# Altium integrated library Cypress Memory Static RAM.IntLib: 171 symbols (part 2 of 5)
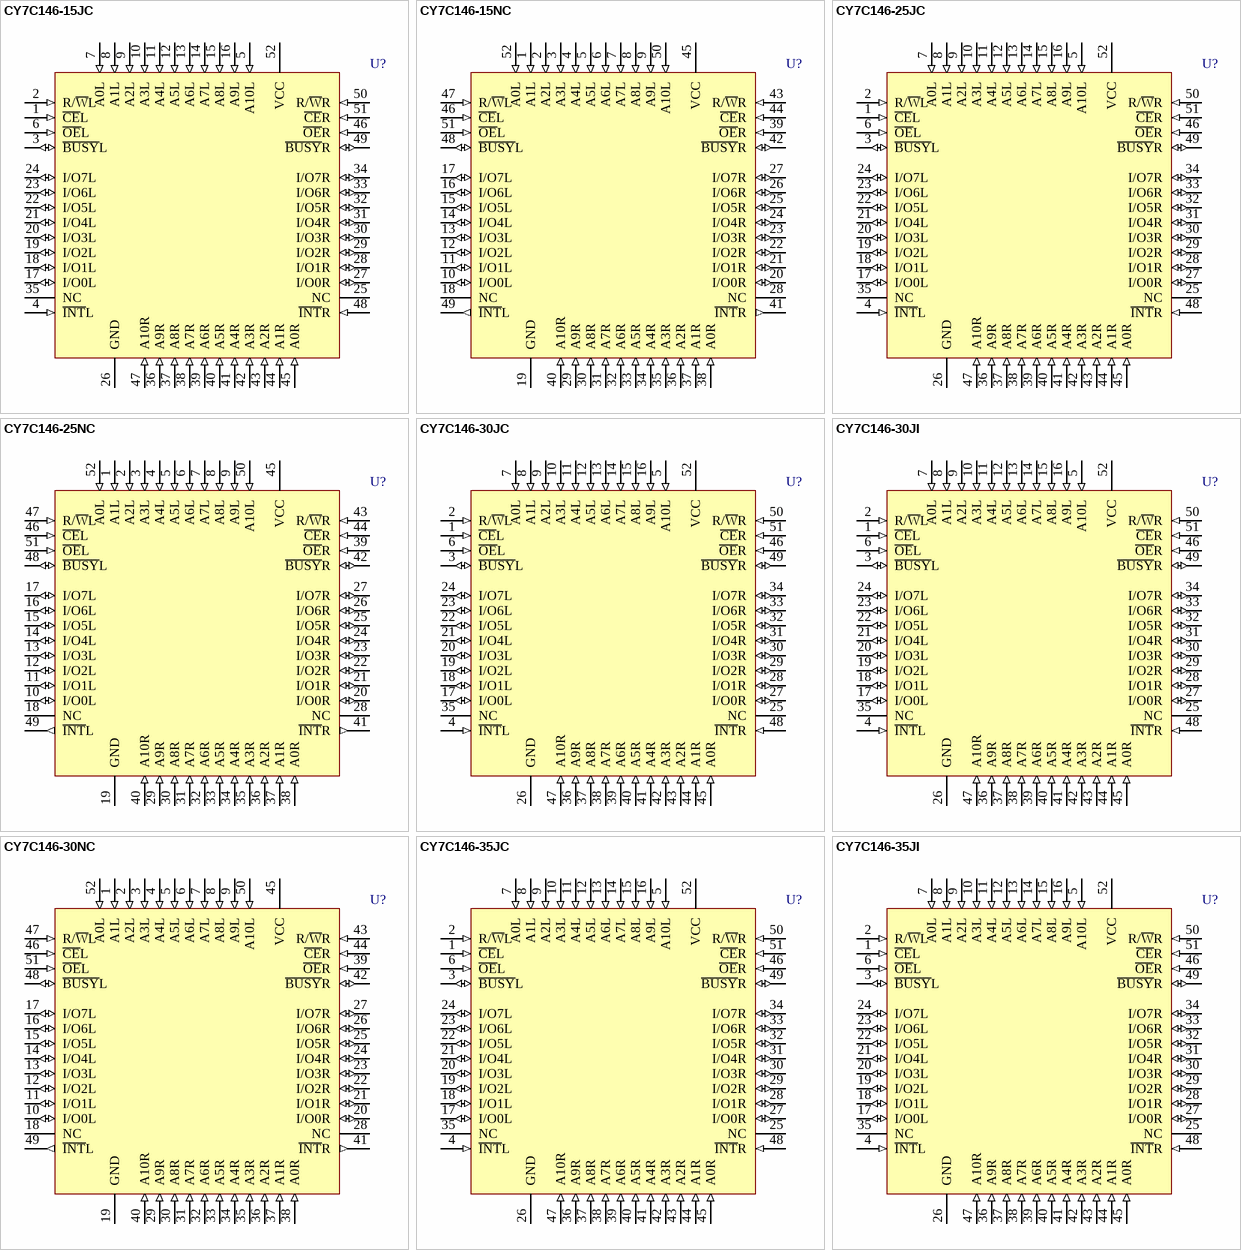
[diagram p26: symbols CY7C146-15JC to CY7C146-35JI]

## CY7C146-35JC
designator U?
2K x 8 Dual-Port Static RAM
footprint J69_N (Leaded Chip Carrier, 52-Leads, Body 19x19mm, Pitch 1.27mm, IPC Medium Density)
footprint J69_L (Leaded Chip Carrier, 52-Leads, Body 19x19mm, Pitch 1.27mm, IPC High Density)
footprint J69_M (Leaded Chip Carrier, 52-Leads, Body 19x19mm, Pitch 1.27mm, IPC Low Density)
3D model CY7C146-J69 (52-Pin Plastic Leaded Chip Carrier 1.27 mm Pitch)
pins: 1 ~{CE}L (in), 2 R/~{W}L (in), 3 ~{BUSY}L (io), 4 ~{INT}L (in), 5 A10L (in), 6 ~{OE}L (in), 7 A0L (in), 8 A1L (in), 9 A2L (in), 10 A3L (in), 11 A4L (in), 12 A5L (in), 13 A6L (in), 14 A7L (in), 15 A8L (in), 16 A9L (in), 17 I/O0L (io), 18 I/O1L (io), 19 I/O2L (io), 20 I/O3L (io), 21 I/O4L (io), 22 I/O5L (io), 23 I/O6L (io), 24 I/O7L (io), 25 NC, 26 GND (power), 27 I/O0R (io), 28 I/O1R (io), 29 I/O2R (io), 30 I/O3R (io), 31 I/O4R (io), 32 I/O5R (io), 33 I/O6R (io), 34 I/O7R (io), 35 NC, 36 A9R (in), 37 A8R (in), 38 A7R (in), 39 A6R (in), 40 A5R (in), 41 A4R (in), 42 A3R (in), 43 A2R (in), 44 A1R (in), 45 A0R (in), 46 ~{OE}R (in), 47 A10R (in), 48 ~{INT}R (in), 49 ~{BUSY}R (io), 50 R/~{W}R (in), 51 ~{CE}R (in), 52 VCC (power)

## CY7C146-35JI
designator U?
2K x 8 Dual-Port Static RAM
footprint J69_N (Leaded Chip Carrier, 52-Leads, Body 19x19mm, Pitch 1.27mm, IPC Medium Density)
footprint J69_L (Leaded Chip Carrier, 52-Leads, Body 19x19mm, Pitch 1.27mm, IPC High Density)
footprint J69_M (Leaded Chip Carrier, 52-Leads, Body 19x19mm, Pitch 1.27mm, IPC Low Density)
3D model CY7C146-J69 (52-Pin Plastic Leaded Chip Carrier 1.27 mm Pitch)
pins: 1 ~{CE}L (in), 2 R/~{W}L (in), 3 ~{BUSY}L (io), 4 ~{INT}L (in), 5 A10L (in), 6 ~{OE}L (in), 7 A0L (in), 8 A1L (in), 9 A2L (in), 10 A3L (in), 11 A4L (in), 12 A5L (in), 13 A6L (in), 14 A7L (in), 15 A8L (in), 16 A9L (in), 17 I/O0L (io), 18 I/O1L (io), 19 I/O2L (io), 20 I/O3L (io), 21 I/O4L (io), 22 I/O5L (io), 23 I/O6L (io), 24 I/O7L (io), 25 NC, 26 GND (power), 27 I/O0R (io), 28 I/O1R (io), 29 I/O2R (io), 30 I/O3R (io), 31 I/O4R (io), 32 I/O5R (io), 33 I/O6R (io), 34 I/O7R (io), 35 NC, 36 A9R (in), 37 A8R (in), 38 A7R (in), 39 A6R (in), 40 A5R (in), 41 A4R (in), 42 A3R (in), 43 A2R (in), 44 A1R (in), 45 A0R (in), 46 ~{OE}R (in), 47 A10R (in), 48 ~{INT}R (in), 49 ~{BUSY}R (io), 50 R/~{W}R (in), 51 ~{CE}R (in), 52 VCC (power)

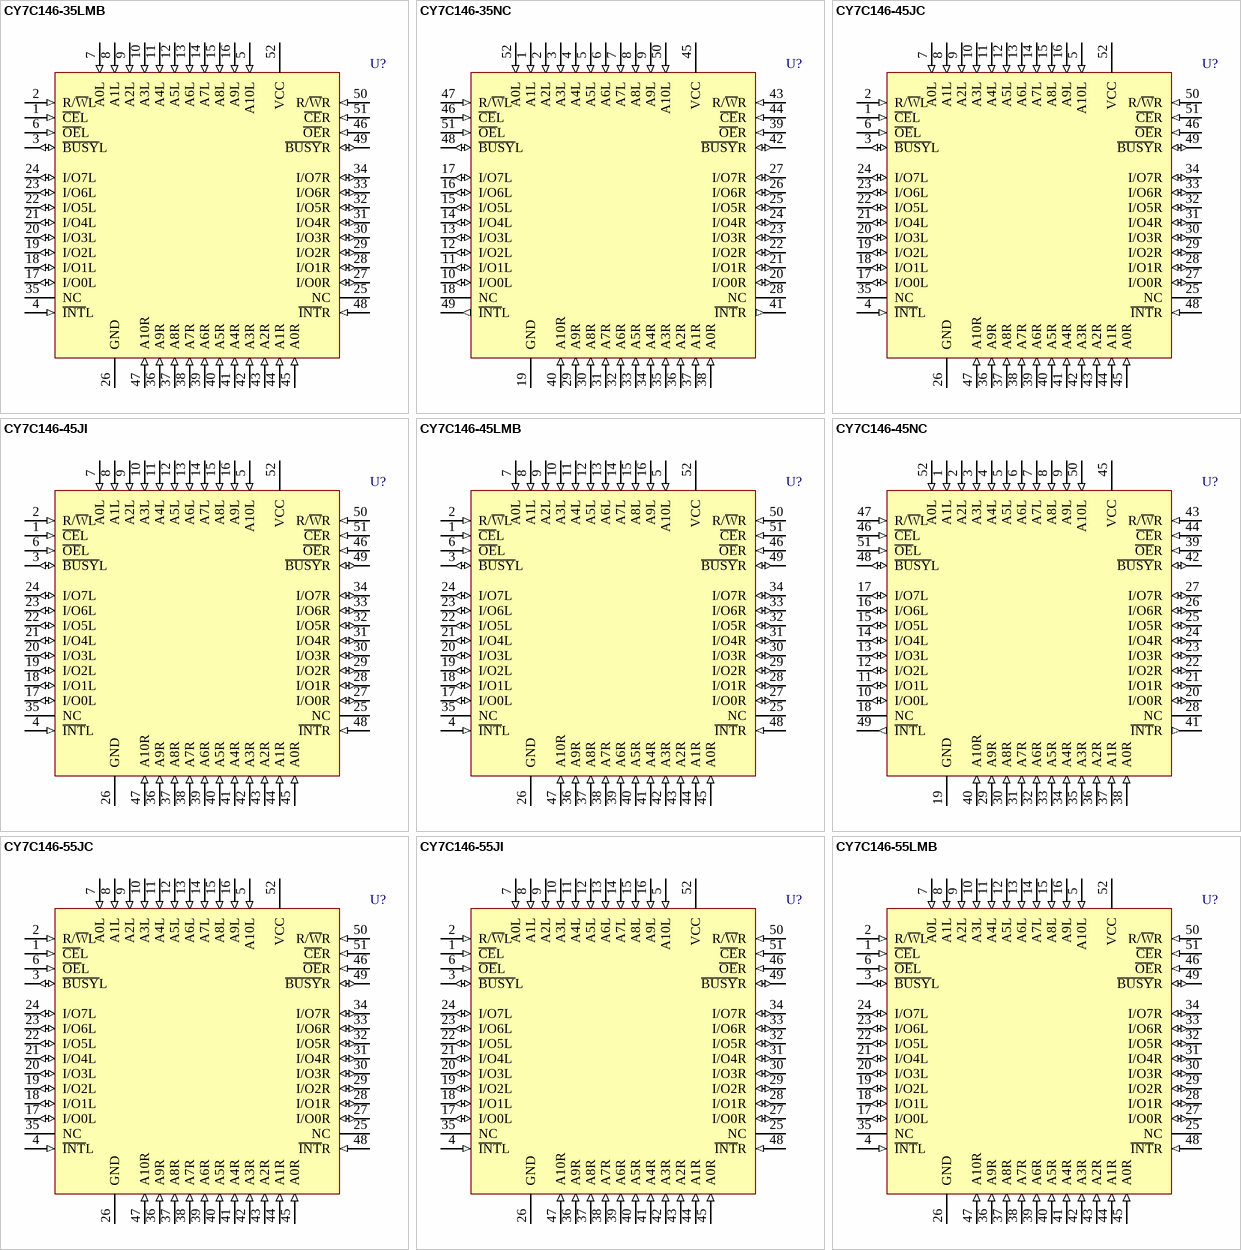
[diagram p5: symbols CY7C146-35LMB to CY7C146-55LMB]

## CY7C146-35LMB
designator U?
2K x 8 Dual-Port Static RAM
footprint L69 (Leadless Chip Carrier; 52 Terminals; Body 19.1 x 19.1 mm)
pins: 1 ~{CE}L (in), 2 R/~{W}L (in), 3 ~{BUSY}L (io), 4 ~{INT}L (in), 5 A10L (in), 6 ~{OE}L (in), 7 A0L (in), 8 A1L (in), 9 A2L (in), 10 A3L (in), 11 A4L (in), 12 A5L (in), 13 A6L (in), 14 A7L (in), 15 A8L (in), 16 A9L (in), 17 I/O0L (io), 18 I/O1L (io), 19 I/O2L (io), 20 I/O3L (io), 21 I/O4L (io), 22 I/O5L (io), 23 I/O6L (io), 24 I/O7L (io), 25 NC, 26 GND (power), 27 I/O0R (io), 28 I/O1R (io), 29 I/O2R (io), 30 I/O3R (io), 31 I/O4R (io), 32 I/O5R (io), 33 I/O6R (io), 34 I/O7R (io), 35 NC, 36 A9R (in), 37 A8R (in), 38 A7R (in), 39 A6R (in), 40 A5R (in), 41 A4R (in), 42 A3R (in), 43 A2R (in), 44 A1R (in), 45 A0R (in), 46 ~{OE}R (in), 47 A10R (in), 48 ~{INT}R (in), 49 ~{BUSY}R (io), 50 R/~{W}R (in), 51 ~{CE}R (in), 52 VCC (power)

## CY7C146-35NC
designator U?
2K x 8 Dual-Port Static RAM
footprint N52_N (QFP, 52-Leads, Body 10 x 10mm, Pitch 0.65mm, IPC Medium Density)
footprint N52_L (QFP, 52-Leads, Body 10 x 10mm, Pitch 0.65mm, IPC High Density)
footprint N52_M (QFP, 52-Leads, Body 10 x 10mm, Pitch 0.65mm, IPC Low Density)
3D model CY7C146-N52 (52-Pin Plastic Quad Flat Pack 0.65 mm Pitch)
pins: 1 A1L (in), 2 A2L (in), 3 A3L (in), 4 A4L (in), 5 A5L (in), 6 A6L (in), 7 A7L (in), 8 A8L (in), 9 A9L (in), 10 I/O0L (io), 11 I/O1L (io), 12 I/O2L (io), 13 I/O3L (io), 14 I/O4L (io), 15 I/O5L (io), 16 I/O6L (io), 17 I/O7L (io), 18 NC, 19 GND (power), 20 I/O0R (io), 21 I/O1R (io), 22 I/O2R (io), 23 I/O3R (io), 24 I/O4R (io), 25 I/O5R (io), 26 I/O6R (io), 27 I/O7R (io), 28 NC, 29 A9R (in), 30 A8R (in), 31 A7R (in), 32 A6R (in), 33 A5R (in), 34 A4R (in), 35 A3R (in), 36 A2R (in), 37 A1R (in), 38 A0R (in), 39 ~{OE}R (in), 40 A10R (in), 41 ~{INT}R (out), 42 ~{BUSY}R (io), 43 R/~{W}R (in), 44 ~{CE}R (in), 45 VCC (power), 46 ~{CE}L (in), 47 R/~{W}L (in), 48 ~{BUSY}L (io), 49 ~{INT}L (out), 50 A10L (in), 51 ~{OE}L (in), 52 A0L (in)

## CY7C146-45JC
designator U?
2K x 8 Dual-Port Static RAM
footprint J69_N (Leaded Chip Carrier, 52-Leads, Body 19x19mm, Pitch 1.27mm, IPC Medium Density)
footprint J69_L (Leaded Chip Carrier, 52-Leads, Body 19x19mm, Pitch 1.27mm, IPC High Density)
footprint J69_M (Leaded Chip Carrier, 52-Leads, Body 19x19mm, Pitch 1.27mm, IPC Low Density)
3D model CY7C146-J69 (52-Pin Plastic Leaded Chip Carrier 1.27 mm Pitch)
pins: 1 ~{CE}L (in), 2 R/~{W}L (in), 3 ~{BUSY}L (io), 4 ~{INT}L (in), 5 A10L (in), 6 ~{OE}L (in), 7 A0L (in), 8 A1L (in), 9 A2L (in), 10 A3L (in), 11 A4L (in), 12 A5L (in), 13 A6L (in), 14 A7L (in), 15 A8L (in), 16 A9L (in), 17 I/O0L (io), 18 I/O1L (io), 19 I/O2L (io), 20 I/O3L (io), 21 I/O4L (io), 22 I/O5L (io), 23 I/O6L (io), 24 I/O7L (io), 25 NC, 26 GND (power), 27 I/O0R (io), 28 I/O1R (io), 29 I/O2R (io), 30 I/O3R (io), 31 I/O4R (io), 32 I/O5R (io), 33 I/O6R (io), 34 I/O7R (io), 35 NC, 36 A9R (in), 37 A8R (in), 38 A7R (in), 39 A6R (in), 40 A5R (in), 41 A4R (in), 42 A3R (in), 43 A2R (in), 44 A1R (in), 45 A0R (in), 46 ~{OE}R (in), 47 A10R (in), 48 ~{INT}R (in), 49 ~{BUSY}R (io), 50 R/~{W}R (in), 51 ~{CE}R (in), 52 VCC (power)

## CY7C146-45JI
designator U?
2K x 8 Dual-Port Static RAM
footprint J69_N (Leaded Chip Carrier, 52-Leads, Body 19x19mm, Pitch 1.27mm, IPC Medium Density)
footprint J69_L (Leaded Chip Carrier, 52-Leads, Body 19x19mm, Pitch 1.27mm, IPC High Density)
footprint J69_M (Leaded Chip Carrier, 52-Leads, Body 19x19mm, Pitch 1.27mm, IPC Low Density)
3D model CY7C146-J69 (52-Pin Plastic Leaded Chip Carrier 1.27 mm Pitch)
pins: 1 ~{CE}L (in), 2 R/~{W}L (in), 3 ~{BUSY}L (io), 4 ~{INT}L (in), 5 A10L (in), 6 ~{OE}L (in), 7 A0L (in), 8 A1L (in), 9 A2L (in), 10 A3L (in), 11 A4L (in), 12 A5L (in), 13 A6L (in), 14 A7L (in), 15 A8L (in), 16 A9L (in), 17 I/O0L (io), 18 I/O1L (io), 19 I/O2L (io), 20 I/O3L (io), 21 I/O4L (io), 22 I/O5L (io), 23 I/O6L (io), 24 I/O7L (io), 25 NC, 26 GND (power), 27 I/O0R (io), 28 I/O1R (io), 29 I/O2R (io), 30 I/O3R (io), 31 I/O4R (io), 32 I/O5R (io), 33 I/O6R (io), 34 I/O7R (io), 35 NC, 36 A9R (in), 37 A8R (in), 38 A7R (in), 39 A6R (in), 40 A5R (in), 41 A4R (in), 42 A3R (in), 43 A2R (in), 44 A1R (in), 45 A0R (in), 46 ~{OE}R (in), 47 A10R (in), 48 ~{INT}R (in), 49 ~{BUSY}R (io), 50 R/~{W}R (in), 51 ~{CE}R (in), 52 VCC (power)

## CY7C146-45LMB
designator U?
2K x 8 Dual-Port Static RAM
footprint L69 (Leadless Chip Carrier; 52 Terminals; Body 19.1 x 19.1 mm)
pins: 1 ~{CE}L (in), 2 R/~{W}L (in), 3 ~{BUSY}L (io), 4 ~{INT}L (in), 5 A10L (in), 6 ~{OE}L (in), 7 A0L (in), 8 A1L (in), 9 A2L (in), 10 A3L (in), 11 A4L (in), 12 A5L (in), 13 A6L (in), 14 A7L (in), 15 A8L (in), 16 A9L (in), 17 I/O0L (io), 18 I/O1L (io), 19 I/O2L (io), 20 I/O3L (io), 21 I/O4L (io), 22 I/O5L (io), 23 I/O6L (io), 24 I/O7L (io), 25 NC, 26 GND (power), 27 I/O0R (io), 28 I/O1R (io), 29 I/O2R (io), 30 I/O3R (io), 31 I/O4R (io), 32 I/O5R (io), 33 I/O6R (io), 34 I/O7R (io), 35 NC, 36 A9R (in), 37 A8R (in), 38 A7R (in), 39 A6R (in), 40 A5R (in), 41 A4R (in), 42 A3R (in), 43 A2R (in), 44 A1R (in), 45 A0R (in), 46 ~{OE}R (in), 47 A10R (in), 48 ~{INT}R (in), 49 ~{BUSY}R (io), 50 R/~{W}R (in), 51 ~{CE}R (in), 52 VCC (power)

## CY7C146-45NC
designator U?
2K x 8 Dual-Port Static RAM
footprint N52_N (QFP, 52-Leads, Body 10 x 10mm, Pitch 0.65mm, IPC Medium Density)
footprint N52_L (QFP, 52-Leads, Body 10 x 10mm, Pitch 0.65mm, IPC High Density)
footprint N52_M (QFP, 52-Leads, Body 10 x 10mm, Pitch 0.65mm, IPC Low Density)
3D model CY7C146-N52 (52-Pin Plastic Quad Flat Pack 0.65 mm Pitch)
pins: 1 A1L (in), 2 A2L (in), 3 A3L (in), 4 A4L (in), 5 A5L (in), 6 A6L (in), 7 A7L (in), 8 A8L (in), 9 A9L (in), 10 I/O0L (io), 11 I/O1L (io), 12 I/O2L (io), 13 I/O3L (io), 14 I/O4L (io), 15 I/O5L (io), 16 I/O6L (io), 17 I/O7L (io), 18 NC, 19 GND (power), 20 I/O0R (io), 21 I/O1R (io), 22 I/O2R (io), 23 I/O3R (io), 24 I/O4R (io), 25 I/O5R (io), 26 I/O6R (io), 27 I/O7R (io), 28 NC, 29 A9R (in), 30 A8R (in), 31 A7R (in), 32 A6R (in), 33 A5R (in), 34 A4R (in), 35 A3R (in), 36 A2R (in), 37 A1R (in), 38 A0R (in), 39 ~{OE}R (in), 40 A10R (in), 41 ~{INT}R (out), 42 ~{BUSY}R (io), 43 R/~{W}R (in), 44 ~{CE}R (in), 45 VCC (power), 46 ~{CE}L (in), 47 R/~{W}L (in), 48 ~{BUSY}L (io), 49 ~{INT}L (out), 50 A10L (in), 51 ~{OE}L (in), 52 A0L (in)

## CY7C146-55JC
designator U?
2K x 8 Dual-Port Static RAM
footprint J69_N (Leaded Chip Carrier, 52-Leads, Body 19x19mm, Pitch 1.27mm, IPC Medium Density)
footprint J69_L (Leaded Chip Carrier, 52-Leads, Body 19x19mm, Pitch 1.27mm, IPC High Density)
footprint J69_M (Leaded Chip Carrier, 52-Leads, Body 19x19mm, Pitch 1.27mm, IPC Low Density)
3D model CY7C146-J69 (52-Pin Plastic Leaded Chip Carrier 1.27 mm Pitch)
pins: 1 ~{CE}L (in), 2 R/~{W}L (in), 3 ~{BUSY}L (io), 4 ~{INT}L (in), 5 A10L (in), 6 ~{OE}L (in), 7 A0L (in), 8 A1L (in), 9 A2L (in), 10 A3L (in), 11 A4L (in), 12 A5L (in), 13 A6L (in), 14 A7L (in), 15 A8L (in), 16 A9L (in), 17 I/O0L (io), 18 I/O1L (io), 19 I/O2L (io), 20 I/O3L (io), 21 I/O4L (io), 22 I/O5L (io), 23 I/O6L (io), 24 I/O7L (io), 25 NC, 26 GND (power), 27 I/O0R (io), 28 I/O1R (io), 29 I/O2R (io), 30 I/O3R (io), 31 I/O4R (io), 32 I/O5R (io), 33 I/O6R (io), 34 I/O7R (io), 35 NC, 36 A9R (in), 37 A8R (in), 38 A7R (in), 39 A6R (in), 40 A5R (in), 41 A4R (in), 42 A3R (in), 43 A2R (in), 44 A1R (in), 45 A0R (in), 46 ~{OE}R (in), 47 A10R (in), 48 ~{INT}R (in), 49 ~{BUSY}R (io), 50 R/~{W}R (in), 51 ~{CE}R (in), 52 VCC (power)

## CY7C146-55JI
designator U?
2K x 8 Dual-Port Static RAM
footprint J69_N (Leaded Chip Carrier, 52-Leads, Body 19x19mm, Pitch 1.27mm, IPC Medium Density)
footprint J69_L (Leaded Chip Carrier, 52-Leads, Body 19x19mm, Pitch 1.27mm, IPC High Density)
footprint J69_M (Leaded Chip Carrier, 52-Leads, Body 19x19mm, Pitch 1.27mm, IPC Low Density)
3D model CY7C146-J69 (52-Pin Plastic Leaded Chip Carrier 1.27 mm Pitch)
pins: 1 ~{CE}L (in), 2 R/~{W}L (in), 3 ~{BUSY}L (io), 4 ~{INT}L (in), 5 A10L (in), 6 ~{OE}L (in), 7 A0L (in), 8 A1L (in), 9 A2L (in), 10 A3L (in), 11 A4L (in), 12 A5L (in), 13 A6L (in), 14 A7L (in), 15 A8L (in), 16 A9L (in), 17 I/O0L (io), 18 I/O1L (io), 19 I/O2L (io), 20 I/O3L (io), 21 I/O4L (io), 22 I/O5L (io), 23 I/O6L (io), 24 I/O7L (io), 25 NC, 26 GND (power), 27 I/O0R (io), 28 I/O1R (io), 29 I/O2R (io), 30 I/O3R (io), 31 I/O4R (io), 32 I/O5R (io), 33 I/O6R (io), 34 I/O7R (io), 35 NC, 36 A9R (in), 37 A8R (in), 38 A7R (in), 39 A6R (in), 40 A5R (in), 41 A4R (in), 42 A3R (in), 43 A2R (in), 44 A1R (in), 45 A0R (in), 46 ~{OE}R (in), 47 A10R (in), 48 ~{INT}R (in), 49 ~{BUSY}R (io), 50 R/~{W}R (in), 51 ~{CE}R (in), 52 VCC (power)

## CY7C146-55LMB
designator U?
2K x 8 Dual-Port Static RAM
footprint L69 (Leadless Chip Carrier; 52 Terminals; Body 19.1 x 19.1 mm)
pins: 1 ~{CE}L (in), 2 R/~{W}L (in), 3 ~{BUSY}L (io), 4 ~{INT}L (in), 5 A10L (in), 6 ~{OE}L (in), 7 A0L (in), 8 A1L (in), 9 A2L (in), 10 A3L (in), 11 A4L (in), 12 A5L (in), 13 A6L (in), 14 A7L (in), 15 A8L (in), 16 A9L (in), 17 I/O0L (io), 18 I/O1L (io), 19 I/O2L (io), 20 I/O3L (io), 21 I/O4L (io), 22 I/O5L (io), 23 I/O6L (io), 24 I/O7L (io), 25 NC, 26 GND (power), 27 I/O0R (io), 28 I/O1R (io), 29 I/O2R (io), 30 I/O3R (io), 31 I/O4R (io), 32 I/O5R (io), 33 I/O6R (io), 34 I/O7R (io), 35 NC, 36 A9R (in), 37 A8R (in), 38 A7R (in), 39 A6R (in), 40 A5R (in), 41 A4R (in), 42 A3R (in), 43 A2R (in), 44 A1R (in), 45 A0R (in), 46 ~{OE}R (in), 47 A10R (in), 48 ~{INT}R (in), 49 ~{BUSY}R (io), 50 R/~{W}R (in), 51 ~{CE}R (in), 52 VCC (power)

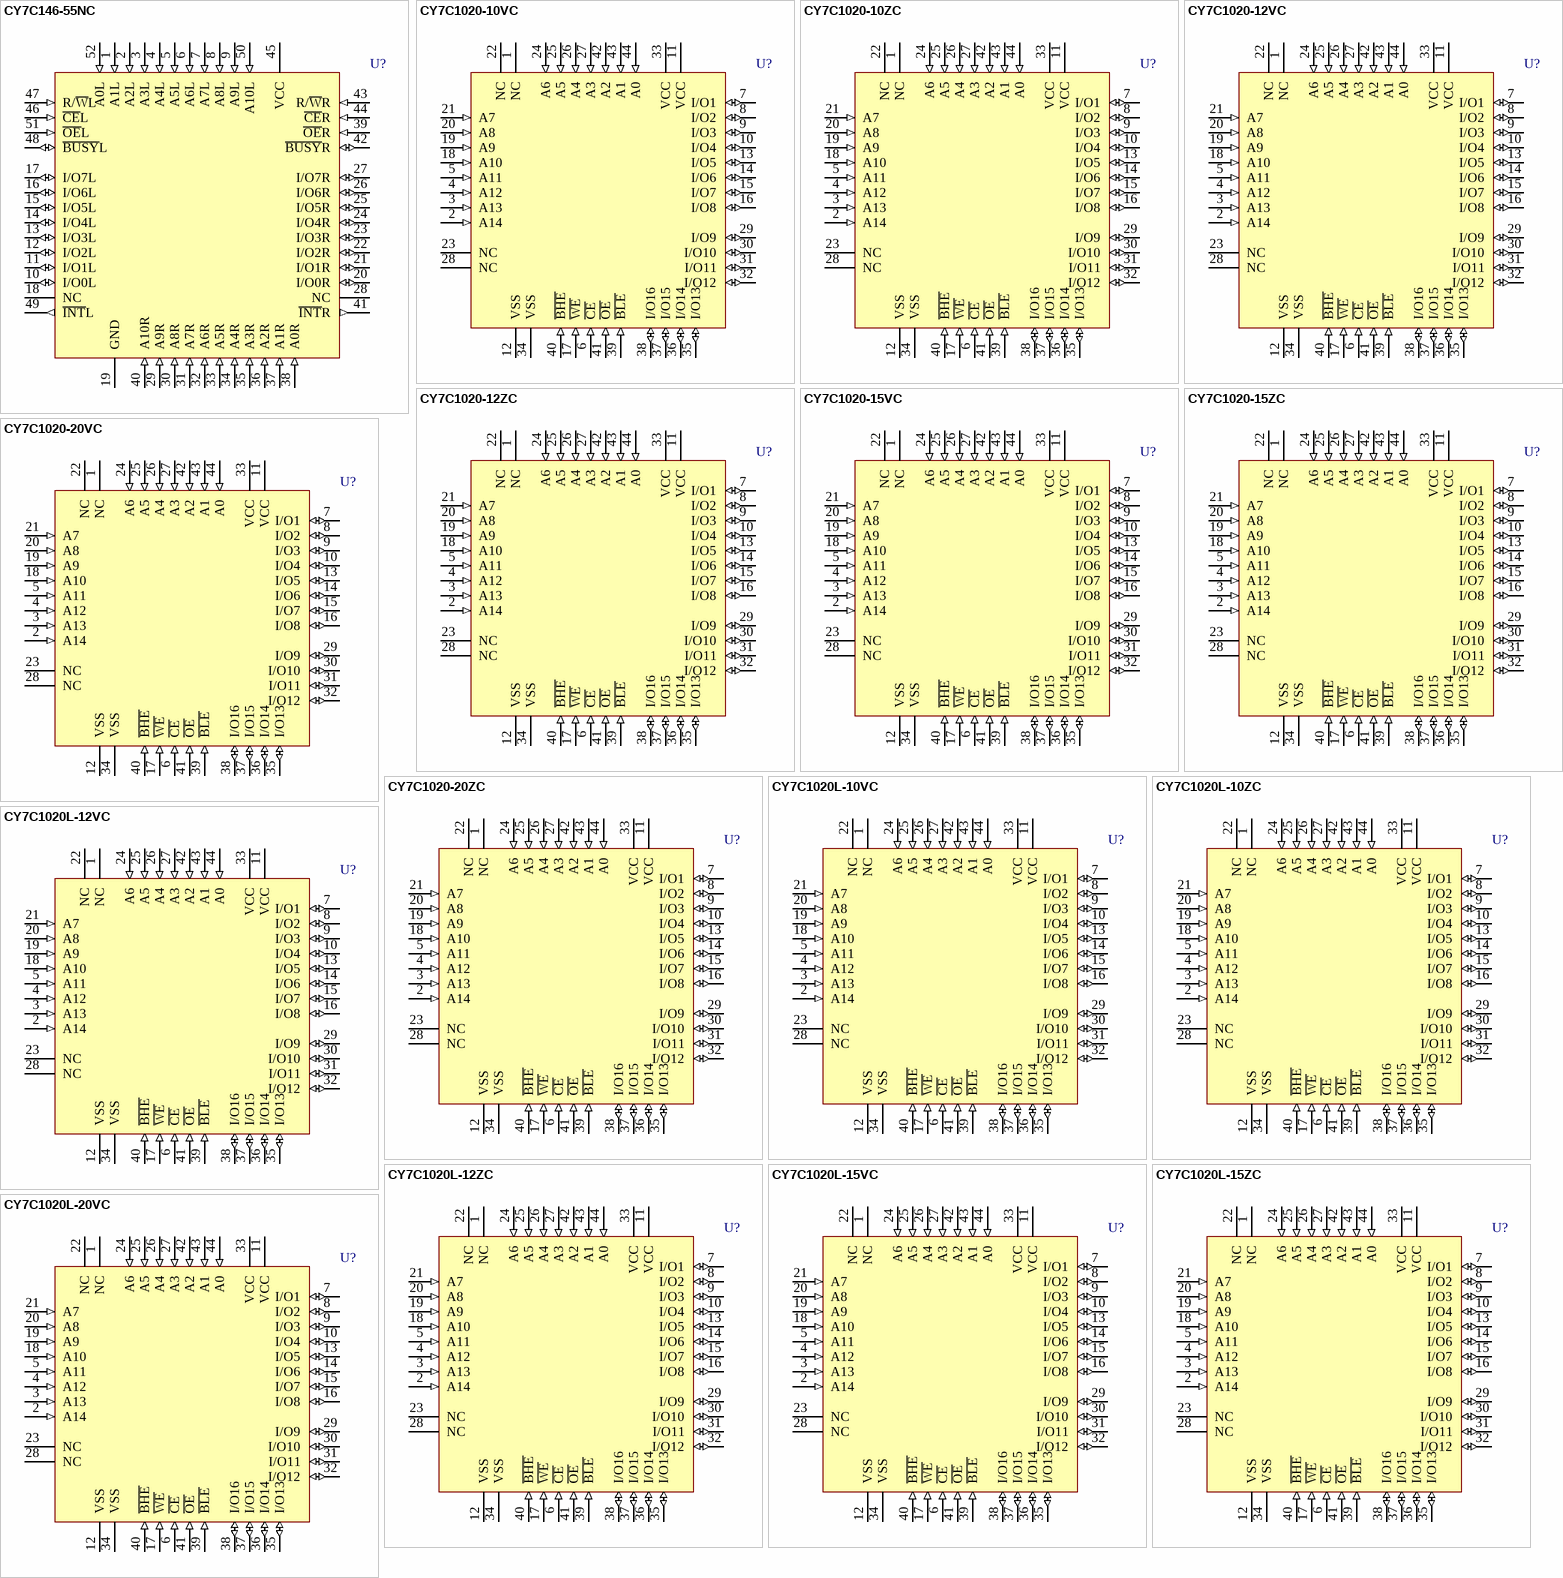
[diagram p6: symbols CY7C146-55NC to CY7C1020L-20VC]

## CY7C146-55NC
designator U?
2K x 8 Dual-Port Static RAM
footprint N52_N (QFP, 52-Leads, Body 10 x 10mm, Pitch 0.65mm, IPC Medium Density)
footprint N52_L (QFP, 52-Leads, Body 10 x 10mm, Pitch 0.65mm, IPC High Density)
footprint N52_M (QFP, 52-Leads, Body 10 x 10mm, Pitch 0.65mm, IPC Low Density)
3D model CY7C146-N52 (52-Pin Plastic Quad Flat Pack 0.65 mm Pitch)
pins: 1 A1L (in), 2 A2L (in), 3 A3L (in), 4 A4L (in), 5 A5L (in), 6 A6L (in), 7 A7L (in), 8 A8L (in), 9 A9L (in), 10 I/O0L (io), 11 I/O1L (io), 12 I/O2L (io), 13 I/O3L (io), 14 I/O4L (io), 15 I/O5L (io), 16 I/O6L (io), 17 I/O7L (io), 18 NC, 19 GND (power), 20 I/O0R (io), 21 I/O1R (io), 22 I/O2R (io), 23 I/O3R (io), 24 I/O4R (io), 25 I/O5R (io), 26 I/O6R (io), 27 I/O7R (io), 28 NC, 29 A9R (in), 30 A8R (in), 31 A7R (in), 32 A6R (in), 33 A5R (in), 34 A4R (in), 35 A3R (in), 36 A2R (in), 37 A1R (in), 38 A0R (in), 39 ~{OE}R (in), 40 A10R (in), 41 ~{INT}R (out), 42 ~{BUSY}R (io), 43 R/~{W}R (in), 44 ~{CE}R (in), 45 VCC (power), 46 ~{CE}L (in), 47 R/~{W}L (in), 48 ~{BUSY}L (io), 49 ~{INT}L (out), 50 A10L (in), 51 ~{OE}L (in), 52 A0L (in)

## CY7C1020-10VC
designator U?
32K x 16 Static RAM
footprint V34 (SOJ, Molded; 44 Leads; Body Width 10.16 mm)
3D model V34 (SOJ, Molded; 44 Leads; Body Width 10.16 mm)
pins: 1 NC, 2 A14 (in), 3 A13 (in), 4 A12 (in), 5 A11 (in), 6 ~{CE} (in), 7 I/O1 (io), 8 I/O2 (io), 9 I/O3 (io), 10 I/O4 (io), 11 VCC (power), 12 VSS (power), 13 I/O5 (io), 14 I/O6 (io), 15 I/O7 (io), 16 I/O8 (io), 17 ~{WE} (in), 18 A10 (in), 19 A9 (in), 20 A8 (in), 21 A7 (in), 22 NC, 23 NC, 24 A6 (in), 25 A5 (in), 26 A4 (in), 27 A3 (in), 28 NC, 29 I/O9 (io), 30 I/O10 (io), 31 I/O11 (io), 32 I/O12 (io), 33 VCC (power), 34 VSS (power), 35 I/O13 (io), 36 I/O14 (io), 37 I/O15 (io), 38 I/O16 (io), 39 ~{BLE} (in), 40 ~{BHE} (in), 41 ~{OE} (in), 42 A2 (in), 43 A1 (in), 44 A0 (in)

## CY7C1020-10ZC
designator U?
32K x 16 Static RAM
footprint Z44_N (SOP, 44-Leads, Body 18.4x10.16mm, Pitch 0.8mm, IPC Medium Density)
footprint Z44_L (SOP, 44-Leads, Body 18.4x10.16mm, Pitch 0.8mm, IPC High Density)
footprint Z44_M (SOP, 44-Leads, Body 18.4x10.16mm, Pitch 0.8mm, IPC Low Density)
3D model Z44 (44-Pin Small Outline Package 0.8 mm Pitch)
pins: 1 NC, 2 A14 (in), 3 A13 (in), 4 A12 (in), 5 A11 (in), 6 ~{CE} (in), 7 I/O1 (io), 8 I/O2 (io), 9 I/O3 (io), 10 I/O4 (io), 11 VCC (power), 12 VSS (power), 13 I/O5 (io), 14 I/O6 (io), 15 I/O7 (io), 16 I/O8 (io), 17 ~{WE} (in), 18 A10 (in), 19 A9 (in), 20 A8 (in), 21 A7 (in), 22 NC, 23 NC, 24 A6 (in), 25 A5 (in), 26 A4 (in), 27 A3 (in), 28 NC, 29 I/O9 (io), 30 I/O10 (io), 31 I/O11 (io), 32 I/O12 (io), 33 VCC (power), 34 VSS (power), 35 I/O13 (io), 36 I/O14 (io), 37 I/O15 (io), 38 I/O16 (io), 39 ~{BLE} (in), 40 ~{BHE} (in), 41 ~{OE} (in), 42 A2 (in), 43 A1 (in), 44 A0 (in)

## CY7C1020-12VC
designator U?
32K x 16 Static RAM
footprint V34 (SOJ, Molded; 44 Leads; Body Width 10.16 mm)
3D model V34 (SOJ, Molded; 44 Leads; Body Width 10.16 mm)
pins: 1 NC, 2 A14 (in), 3 A13 (in), 4 A12 (in), 5 A11 (in), 6 ~{CE} (in), 7 I/O1 (io), 8 I/O2 (io), 9 I/O3 (io), 10 I/O4 (io), 11 VCC (power), 12 VSS (power), 13 I/O5 (io), 14 I/O6 (io), 15 I/O7 (io), 16 I/O8 (io), 17 ~{WE} (in), 18 A10 (in), 19 A9 (in), 20 A8 (in), 21 A7 (in), 22 NC, 23 NC, 24 A6 (in), 25 A5 (in), 26 A4 (in), 27 A3 (in), 28 NC, 29 I/O9 (io), 30 I/O10 (io), 31 I/O11 (io), 32 I/O12 (io), 33 VCC (power), 34 VSS (power), 35 I/O13 (io), 36 I/O14 (io), 37 I/O15 (io), 38 I/O16 (io), 39 ~{BLE} (in), 40 ~{BHE} (in), 41 ~{OE} (in), 42 A2 (in), 43 A1 (in), 44 A0 (in)

## CY7C1020-12ZC
designator U?
32K x 16 Static RAM
footprint Z44_N (SOP, 44-Leads, Body 18.4x10.16mm, Pitch 0.8mm, IPC Medium Density)
footprint Z44_L (SOP, 44-Leads, Body 18.4x10.16mm, Pitch 0.8mm, IPC High Density)
footprint Z44_M (SOP, 44-Leads, Body 18.4x10.16mm, Pitch 0.8mm, IPC Low Density)
3D model Z44 (44-Pin Small Outline Package 0.8 mm Pitch)
pins: 1 NC, 2 A14 (in), 3 A13 (in), 4 A12 (in), 5 A11 (in), 6 ~{CE} (in), 7 I/O1 (io), 8 I/O2 (io), 9 I/O3 (io), 10 I/O4 (io), 11 VCC (power), 12 VSS (power), 13 I/O5 (io), 14 I/O6 (io), 15 I/O7 (io), 16 I/O8 (io), 17 ~{WE} (in), 18 A10 (in), 19 A9 (in), 20 A8 (in), 21 A7 (in), 22 NC, 23 NC, 24 A6 (in), 25 A5 (in), 26 A4 (in), 27 A3 (in), 28 NC, 29 I/O9 (io), 30 I/O10 (io), 31 I/O11 (io), 32 I/O12 (io), 33 VCC (power), 34 VSS (power), 35 I/O13 (io), 36 I/O14 (io), 37 I/O15 (io), 38 I/O16 (io), 39 ~{BLE} (in), 40 ~{BHE} (in), 41 ~{OE} (in), 42 A2 (in), 43 A1 (in), 44 A0 (in)

## CY7C1020-15VC
designator U?
32K x 16 Static RAM
footprint V34 (SOJ, Molded; 44 Leads; Body Width 10.16 mm)
3D model V34 (SOJ, Molded; 44 Leads; Body Width 10.16 mm)
pins: 1 NC, 2 A14 (in), 3 A13 (in), 4 A12 (in), 5 A11 (in), 6 ~{CE} (in), 7 I/O1 (io), 8 I/O2 (io), 9 I/O3 (io), 10 I/O4 (io), 11 VCC (power), 12 VSS (power), 13 I/O5 (io), 14 I/O6 (io), 15 I/O7 (io), 16 I/O8 (io), 17 ~{WE} (in), 18 A10 (in), 19 A9 (in), 20 A8 (in), 21 A7 (in), 22 NC, 23 NC, 24 A6 (in), 25 A5 (in), 26 A4 (in), 27 A3 (in), 28 NC, 29 I/O9 (io), 30 I/O10 (io), 31 I/O11 (io), 32 I/O12 (io), 33 VCC (power), 34 VSS (power), 35 I/O13 (io), 36 I/O14 (io), 37 I/O15 (io), 38 I/O16 (io), 39 ~{BLE} (in), 40 ~{BHE} (in), 41 ~{OE} (in), 42 A2 (in), 43 A1 (in), 44 A0 (in)

## CY7C1020-15ZC
designator U?
32K x 16 Static RAM
footprint Z44_N (SOP, 44-Leads, Body 18.4x10.16mm, Pitch 0.8mm, IPC Medium Density)
footprint Z44_L (SOP, 44-Leads, Body 18.4x10.16mm, Pitch 0.8mm, IPC High Density)
footprint Z44_M (SOP, 44-Leads, Body 18.4x10.16mm, Pitch 0.8mm, IPC Low Density)
3D model Z44 (44-Pin Small Outline Package 0.8 mm Pitch)
pins: 1 NC, 2 A14 (in), 3 A13 (in), 4 A12 (in), 5 A11 (in), 6 ~{CE} (in), 7 I/O1 (io), 8 I/O2 (io), 9 I/O3 (io), 10 I/O4 (io), 11 VCC (power), 12 VSS (power), 13 I/O5 (io), 14 I/O6 (io), 15 I/O7 (io), 16 I/O8 (io), 17 ~{WE} (in), 18 A10 (in), 19 A9 (in), 20 A8 (in), 21 A7 (in), 22 NC, 23 NC, 24 A6 (in), 25 A5 (in), 26 A4 (in), 27 A3 (in), 28 NC, 29 I/O9 (io), 30 I/O10 (io), 31 I/O11 (io), 32 I/O12 (io), 33 VCC (power), 34 VSS (power), 35 I/O13 (io), 36 I/O14 (io), 37 I/O15 (io), 38 I/O16 (io), 39 ~{BLE} (in), 40 ~{BHE} (in), 41 ~{OE} (in), 42 A2 (in), 43 A1 (in), 44 A0 (in)

## CY7C1020-20VC
designator U?
32K x 16 Static RAM
footprint V34 (SOJ, Molded; 44 Leads; Body Width 10.16 mm)
3D model V34 (SOJ, Molded; 44 Leads; Body Width 10.16 mm)
pins: 1 NC, 2 A14 (in), 3 A13 (in), 4 A12 (in), 5 A11 (in), 6 ~{CE} (in), 7 I/O1 (io), 8 I/O2 (io), 9 I/O3 (io), 10 I/O4 (io), 11 VCC (power), 12 VSS (power), 13 I/O5 (io), 14 I/O6 (io), 15 I/O7 (io), 16 I/O8 (io), 17 ~{WE} (in), 18 A10 (in), 19 A9 (in), 20 A8 (in), 21 A7 (in), 22 NC, 23 NC, 24 A6 (in), 25 A5 (in), 26 A4 (in), 27 A3 (in), 28 NC, 29 I/O9 (io), 30 I/O10 (io), 31 I/O11 (io), 32 I/O12 (io), 33 VCC (power), 34 VSS (power), 35 I/O13 (io), 36 I/O14 (io), 37 I/O15 (io), 38 I/O16 (io), 39 ~{BLE} (in), 40 ~{BHE} (in), 41 ~{OE} (in), 42 A2 (in), 43 A1 (in), 44 A0 (in)

## CY7C1020-20ZC
designator U?
32K x 16 Static RAM
footprint Z44_N (SOP, 44-Leads, Body 18.4x10.16mm, Pitch 0.8mm, IPC Medium Density)
footprint Z44_L (SOP, 44-Leads, Body 18.4x10.16mm, Pitch 0.8mm, IPC High Density)
footprint Z44_M (SOP, 44-Leads, Body 18.4x10.16mm, Pitch 0.8mm, IPC Low Density)
3D model Z44 (44-Pin Small Outline Package 0.8 mm Pitch)
pins: 1 NC, 2 A14 (in), 3 A13 (in), 4 A12 (in), 5 A11 (in), 6 ~{CE} (in), 7 I/O1 (io), 8 I/O2 (io), 9 I/O3 (io), 10 I/O4 (io), 11 VCC (power), 12 VSS (power), 13 I/O5 (io), 14 I/O6 (io), 15 I/O7 (io), 16 I/O8 (io), 17 ~{WE} (in), 18 A10 (in), 19 A9 (in), 20 A8 (in), 21 A7 (in), 22 NC, 23 NC, 24 A6 (in), 25 A5 (in), 26 A4 (in), 27 A3 (in), 28 NC, 29 I/O9 (io), 30 I/O10 (io), 31 I/O11 (io), 32 I/O12 (io), 33 VCC (power), 34 VSS (power), 35 I/O13 (io), 36 I/O14 (io), 37 I/O15 (io), 38 I/O16 (io), 39 ~{BLE} (in), 40 ~{BHE} (in), 41 ~{OE} (in), 42 A2 (in), 43 A1 (in), 44 A0 (in)

## CY7C1020L-10VC
designator U?
32K x 16 Static RAM
footprint V34 (SOJ, Molded; 44 Leads; Body Width 10.16 mm)
3D model V34 (SOJ, Molded; 44 Leads; Body Width 10.16 mm)
pins: 1 NC, 2 A14 (in), 3 A13 (in), 4 A12 (in), 5 A11 (in), 6 ~{CE} (in), 7 I/O1 (io), 8 I/O2 (io), 9 I/O3 (io), 10 I/O4 (io), 11 VCC (power), 12 VSS (power), 13 I/O5 (io), 14 I/O6 (io), 15 I/O7 (io), 16 I/O8 (io), 17 ~{WE} (in), 18 A10 (in), 19 A9 (in), 20 A8 (in), 21 A7 (in), 22 NC, 23 NC, 24 A6 (in), 25 A5 (in), 26 A4 (in), 27 A3 (in), 28 NC, 29 I/O9 (io), 30 I/O10 (io), 31 I/O11 (io), 32 I/O12 (io), 33 VCC (power), 34 VSS (power), 35 I/O13 (io), 36 I/O14 (io), 37 I/O15 (io), 38 I/O16 (io), 39 ~{BLE} (in), 40 ~{BHE} (in), 41 ~{OE} (in), 42 A2 (in), 43 A1 (in), 44 A0 (in)

## CY7C1020L-10ZC
designator U?
32K x 16 Static RAM
footprint Z44_N (SOP, 44-Leads, Body 18.4x10.16mm, Pitch 0.8mm, IPC Medium Density)
footprint Z44_L (SOP, 44-Leads, Body 18.4x10.16mm, Pitch 0.8mm, IPC High Density)
footprint Z44_M (SOP, 44-Leads, Body 18.4x10.16mm, Pitch 0.8mm, IPC Low Density)
3D model Z44 (44-Pin Small Outline Package 0.8 mm Pitch)
pins: 1 NC, 2 A14 (in), 3 A13 (in), 4 A12 (in), 5 A11 (in), 6 ~{CE} (in), 7 I/O1 (io), 8 I/O2 (io), 9 I/O3 (io), 10 I/O4 (io), 11 VCC (power), 12 VSS (power), 13 I/O5 (io), 14 I/O6 (io), 15 I/O7 (io), 16 I/O8 (io), 17 ~{WE} (in), 18 A10 (in), 19 A9 (in), 20 A8 (in), 21 A7 (in), 22 NC, 23 NC, 24 A6 (in), 25 A5 (in), 26 A4 (in), 27 A3 (in), 28 NC, 29 I/O9 (io), 30 I/O10 (io), 31 I/O11 (io), 32 I/O12 (io), 33 VCC (power), 34 VSS (power), 35 I/O13 (io), 36 I/O14 (io), 37 I/O15 (io), 38 I/O16 (io), 39 ~{BLE} (in), 40 ~{BHE} (in), 41 ~{OE} (in), 42 A2 (in), 43 A1 (in), 44 A0 (in)

## CY7C1020L-12VC
designator U?
32K x 16 Static RAM
footprint V34 (SOJ, Molded; 44 Leads; Body Width 10.16 mm)
3D model V34 (SOJ, Molded; 44 Leads; Body Width 10.16 mm)
pins: 1 NC, 2 A14 (in), 3 A13 (in), 4 A12 (in), 5 A11 (in), 6 ~{CE} (in), 7 I/O1 (io), 8 I/O2 (io), 9 I/O3 (io), 10 I/O4 (io), 11 VCC (power), 12 VSS (power), 13 I/O5 (io), 14 I/O6 (io), 15 I/O7 (io), 16 I/O8 (io), 17 ~{WE} (in), 18 A10 (in), 19 A9 (in), 20 A8 (in), 21 A7 (in), 22 NC, 23 NC, 24 A6 (in), 25 A5 (in), 26 A4 (in), 27 A3 (in), 28 NC, 29 I/O9 (io), 30 I/O10 (io), 31 I/O11 (io), 32 I/O12 (io), 33 VCC (power), 34 VSS (power), 35 I/O13 (io), 36 I/O14 (io), 37 I/O15 (io), 38 I/O16 (io), 39 ~{BLE} (in), 40 ~{BHE} (in), 41 ~{OE} (in), 42 A2 (in), 43 A1 (in), 44 A0 (in)

## CY7C1020L-12ZC
designator U?
32K x 16 Static RAM
footprint Z44_N (SOP, 44-Leads, Body 18.4x10.16mm, Pitch 0.8mm, IPC Medium Density)
footprint Z44_L (SOP, 44-Leads, Body 18.4x10.16mm, Pitch 0.8mm, IPC High Density)
footprint Z44_M (SOP, 44-Leads, Body 18.4x10.16mm, Pitch 0.8mm, IPC Low Density)
3D model Z44 (44-Pin Small Outline Package 0.8 mm Pitch)
pins: 1 NC, 2 A14 (in), 3 A13 (in), 4 A12 (in), 5 A11 (in), 6 ~{CE} (in), 7 I/O1 (io), 8 I/O2 (io), 9 I/O3 (io), 10 I/O4 (io), 11 VCC (power), 12 VSS (power), 13 I/O5 (io), 14 I/O6 (io), 15 I/O7 (io), 16 I/O8 (io), 17 ~{WE} (in), 18 A10 (in), 19 A9 (in), 20 A8 (in), 21 A7 (in), 22 NC, 23 NC, 24 A6 (in), 25 A5 (in), 26 A4 (in), 27 A3 (in), 28 NC, 29 I/O9 (io), 30 I/O10 (io), 31 I/O11 (io), 32 I/O12 (io), 33 VCC (power), 34 VSS (power), 35 I/O13 (io), 36 I/O14 (io), 37 I/O15 (io), 38 I/O16 (io), 39 ~{BLE} (in), 40 ~{BHE} (in), 41 ~{OE} (in), 42 A2 (in), 43 A1 (in), 44 A0 (in)

## CY7C1020L-15VC
designator U?
32K x 16 Static RAM
footprint V34 (SOJ, Molded; 44 Leads; Body Width 10.16 mm)
3D model V34 (SOJ, Molded; 44 Leads; Body Width 10.16 mm)
pins: 1 NC, 2 A14 (in), 3 A13 (in), 4 A12 (in), 5 A11 (in), 6 ~{CE} (in), 7 I/O1 (io), 8 I/O2 (io), 9 I/O3 (io), 10 I/O4 (io), 11 VCC (power), 12 VSS (power), 13 I/O5 (io), 14 I/O6 (io), 15 I/O7 (io), 16 I/O8 (io), 17 ~{WE} (in), 18 A10 (in), 19 A9 (in), 20 A8 (in), 21 A7 (in), 22 NC, 23 NC, 24 A6 (in), 25 A5 (in), 26 A4 (in), 27 A3 (in), 28 NC, 29 I/O9 (io), 30 I/O10 (io), 31 I/O11 (io), 32 I/O12 (io), 33 VCC (power), 34 VSS (power), 35 I/O13 (io), 36 I/O14 (io), 37 I/O15 (io), 38 I/O16 (io), 39 ~{BLE} (in), 40 ~{BHE} (in), 41 ~{OE} (in), 42 A2 (in), 43 A1 (in), 44 A0 (in)

## CY7C1020L-15ZC
designator U?
32K x 16 Static RAM
footprint Z44_N (SOP, 44-Leads, Body 18.4x10.16mm, Pitch 0.8mm, IPC Medium Density)
footprint Z44_L (SOP, 44-Leads, Body 18.4x10.16mm, Pitch 0.8mm, IPC High Density)
footprint Z44_M (SOP, 44-Leads, Body 18.4x10.16mm, Pitch 0.8mm, IPC Low Density)
3D model Z44 (44-Pin Small Outline Package 0.8 mm Pitch)
pins: 1 NC, 2 A14 (in), 3 A13 (in), 4 A12 (in), 5 A11 (in), 6 ~{CE} (in), 7 I/O1 (io), 8 I/O2 (io), 9 I/O3 (io), 10 I/O4 (io), 11 VCC (power), 12 VSS (power), 13 I/O5 (io), 14 I/O6 (io), 15 I/O7 (io), 16 I/O8 (io), 17 ~{WE} (in), 18 A10 (in), 19 A9 (in), 20 A8 (in), 21 A7 (in), 22 NC, 23 NC, 24 A6 (in), 25 A5 (in), 26 A4 (in), 27 A3 (in), 28 NC, 29 I/O9 (io), 30 I/O10 (io), 31 I/O11 (io), 32 I/O12 (io), 33 VCC (power), 34 VSS (power), 35 I/O13 (io), 36 I/O14 (io), 37 I/O15 (io), 38 I/O16 (io), 39 ~{BLE} (in), 40 ~{BHE} (in), 41 ~{OE} (in), 42 A2 (in), 43 A1 (in), 44 A0 (in)

## CY7C1020L-20VC
designator U?
32K x 16 Static RAM
footprint V34 (SOJ, Molded; 44 Leads; Body Width 10.16 mm)
3D model V34 (SOJ, Molded; 44 Leads; Body Width 10.16 mm)
pins: 1 NC, 2 A14 (in), 3 A13 (in), 4 A12 (in), 5 A11 (in), 6 ~{CE} (in), 7 I/O1 (io), 8 I/O2 (io), 9 I/O3 (io), 10 I/O4 (io), 11 VCC (power), 12 VSS (power), 13 I/O5 (io), 14 I/O6 (io), 15 I/O7 (io), 16 I/O8 (io), 17 ~{WE} (in), 18 A10 (in), 19 A9 (in), 20 A8 (in), 21 A7 (in), 22 NC, 23 NC, 24 A6 (in), 25 A5 (in), 26 A4 (in), 27 A3 (in), 28 NC, 29 I/O9 (io), 30 I/O10 (io), 31 I/O11 (io), 32 I/O12 (io), 33 VCC (power), 34 VSS (power), 35 I/O13 (io), 36 I/O14 (io), 37 I/O15 (io), 38 I/O16 (io), 39 ~{BLE} (in), 40 ~{BHE} (in), 41 ~{OE} (in), 42 A2 (in), 43 A1 (in), 44 A0 (in)

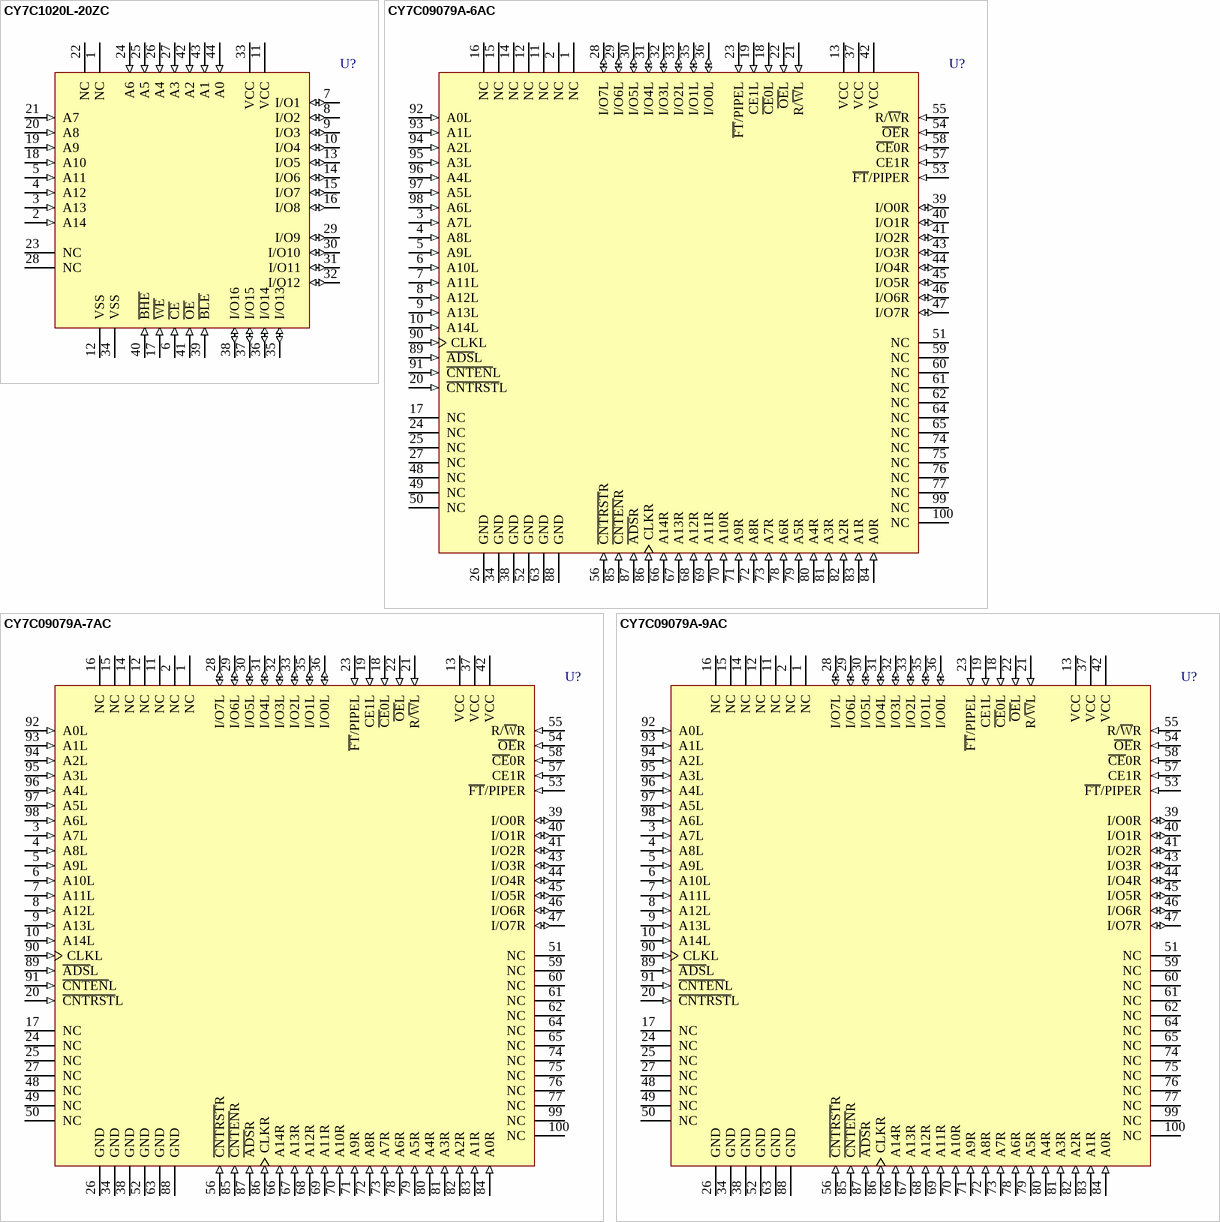
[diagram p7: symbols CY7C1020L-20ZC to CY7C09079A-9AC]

## CY7C1020L-20ZC
designator U?
32K x 16 Static RAM
footprint Z44_N (SOP, 44-Leads, Body 18.4x10.16mm, Pitch 0.8mm, IPC Medium Density)
footprint Z44_L (SOP, 44-Leads, Body 18.4x10.16mm, Pitch 0.8mm, IPC High Density)
footprint Z44_M (SOP, 44-Leads, Body 18.4x10.16mm, Pitch 0.8mm, IPC Low Density)
3D model Z44 (44-Pin Small Outline Package 0.8 mm Pitch)
pins: 1 NC, 2 A14 (in), 3 A13 (in), 4 A12 (in), 5 A11 (in), 6 ~{CE} (in), 7 I/O1 (io), 8 I/O2 (io), 9 I/O3 (io), 10 I/O4 (io), 11 VCC (power), 12 VSS (power), 13 I/O5 (io), 14 I/O6 (io), 15 I/O7 (io), 16 I/O8 (io), 17 ~{WE} (in), 18 A10 (in), 19 A9 (in), 20 A8 (in), 21 A7 (in), 22 NC, 23 NC, 24 A6 (in), 25 A5 (in), 26 A4 (in), 27 A3 (in), 28 NC, 29 I/O9 (io), 30 I/O10 (io), 31 I/O11 (io), 32 I/O12 (io), 33 VCC (power), 34 VSS (power), 35 I/O13 (io), 36 I/O14 (io), 37 I/O15 (io), 38 I/O16 (io), 39 ~{BLE} (in), 40 ~{BHE} (in), 41 ~{OE} (in), 42 A2 (in), 43 A1 (in), 44 A0 (in)

## CY7C09079A-6AC
designator U?
32K x 8 Synchronous Dual-Port RAM
footprint A100_N (Thin QFP, 100-Leads, Body 14x14mm, Pitch 0.5mm, IPC Medium Density)
footprint A100_L (Thin QFP, 100-Leads, Body 14x14mm, Pitch 0.5mm, IPC High Density)
footprint A100_M (Thin QFP, 100-Leads, Body 14x14mm, Pitch 0.5mm, IPC Low Density)
3D model CY7C09079A-A100 (100-Pin Thin Quad Flat Pack 0.5 mm Pitch)
pins: 1 NC, 2 NC, 3 A7L (in), 4 A8L (in), 5 A9L (in), 6 A10L (in), 7 A11L (in), 8 A12L (in), 9 A13L (in), 10 A14L (in), 11 NC, 12 NC, 13 VCC (power), 14 NC, 15 NC, 16 NC, 17 NC, 18 ~{CE}0L (in), 19 CE1L (in), 20 ~{CNTRST}L (in), 21 R/~{W}L (in), 22 ~{OE}L (in), 23 ~{FT}/PIPEL (in), 24 NC, 25 NC, 26 GND (power), 27 NC, 28 I/O7L (io), 29 I/O6L (io), 30 I/O5L (io), 31 I/O4L (io), 32 I/O3L (io), 33 I/O2L (io), 34 GND (power), 35 I/O1L (io), 36 I/O0L (io), 37 VCC (power), 38 GND (power), 39 I/O0R (io), 40 I/O1R (io), 41 I/O2R (io), 42 VCC (power), 43 I/O3R (io), 44 I/O4R (io), 45 I/O5R (io), 46 I/O6R (io), 47 I/O7R (io), 48 NC, 49 NC, 50 NC, 51 NC, 52 GND (power), 53 ~{FT}/PIPER (in), 54 ~{OE}R (in), 55 R/~{W}R (in), 56 ~{CNTRST}R (in), 57 CE1R (in), 58 ~{CE}0R (in), 59 NC, 60 NC, 61 NC, 62 NC, 63 GND (power), 64 NC, 65 NC, 66 A14R (in), 67 A13R (in), 68 A12R (in), 69 A11R (in), 70 A10R (in), 71 A9R (in), 72 A8R (in), 73 A7R (in), 74 NC, 75 NC, 76 NC, 77 NC, 78 A6R (in), 79 A5R (in), 80 A4R (in), 81 A3R (in), 82 A2R (in), 83 A1R (in), 84 A0R (in), 85 ~{CNTEN}R (in), 86 CLKR (in), 87 ~{ADS}R (in), 88 GND (power), 89 ~{ADS}L (in), 90 CLKL (in), 91 ~{CNTEN}L (in), 92 A0L (in), 93 A1L (in), 94 A2L (in), 95 A3L (in), 96 A4L (in), 97 A5L (in), 98 A6L (in), 99 NC, 100 NC

## CY7C09079A-7AC
designator U?
32K x 8 Synchronous Dual-Port RAM
footprint A100_N (Thin QFP, 100-Leads, Body 14x14mm, Pitch 0.5mm, IPC Medium Density)
footprint A100_L (Thin QFP, 100-Leads, Body 14x14mm, Pitch 0.5mm, IPC High Density)
footprint A100_M (Thin QFP, 100-Leads, Body 14x14mm, Pitch 0.5mm, IPC Low Density)
3D model CY7C09079A-A100 (100-Pin Thin Quad Flat Pack 0.5 mm Pitch)
pins: 1 NC, 2 NC, 3 A7L (in), 4 A8L (in), 5 A9L (in), 6 A10L (in), 7 A11L (in), 8 A12L (in), 9 A13L (in), 10 A14L (in), 11 NC, 12 NC, 13 VCC (power), 14 NC, 15 NC, 16 NC, 17 NC, 18 ~{CE}0L (in), 19 CE1L (in), 20 ~{CNTRST}L (in), 21 R/~{W}L (in), 22 ~{OE}L (in), 23 ~{FT}/PIPEL (in), 24 NC, 25 NC, 26 GND (power), 27 NC, 28 I/O7L (io), 29 I/O6L (io), 30 I/O5L (io), 31 I/O4L (io), 32 I/O3L (io), 33 I/O2L (io), 34 GND (power), 35 I/O1L (io), 36 I/O0L (io), 37 VCC (power), 38 GND (power), 39 I/O0R (io), 40 I/O1R (io), 41 I/O2R (io), 42 VCC (power), 43 I/O3R (io), 44 I/O4R (io), 45 I/O5R (io), 46 I/O6R (io), 47 I/O7R (io), 48 NC, 49 NC, 50 NC, 51 NC, 52 GND (power), 53 ~{FT}/PIPER (in), 54 ~{OE}R (in), 55 R/~{W}R (in), 56 ~{CNTRST}R (in), 57 CE1R (in), 58 ~{CE}0R (in), 59 NC, 60 NC, 61 NC, 62 NC, 63 GND (power), 64 NC, 65 NC, 66 A14R (in), 67 A13R (in), 68 A12R (in), 69 A11R (in), 70 A10R (in), 71 A9R (in), 72 A8R (in), 73 A7R (in), 74 NC, 75 NC, 76 NC, 77 NC, 78 A6R (in), 79 A5R (in), 80 A4R (in), 81 A3R (in), 82 A2R (in), 83 A1R (in), 84 A0R (in), 85 ~{CNTEN}R (in), 86 CLKR (in), 87 ~{ADS}R (in), 88 GND (power), 89 ~{ADS}L (in), 90 CLKL (in), 91 ~{CNTEN}L (in), 92 A0L (in), 93 A1L (in), 94 A2L (in), 95 A3L (in), 96 A4L (in), 97 A5L (in), 98 A6L (in), 99 NC, 100 NC

## CY7C09079A-9AC
designator U?
32K x 8 Synchronous Dual-Port RAM
footprint A100_N (Thin QFP, 100-Leads, Body 14x14mm, Pitch 0.5mm, IPC Medium Density)
footprint A100_L (Thin QFP, 100-Leads, Body 14x14mm, Pitch 0.5mm, IPC High Density)
footprint A100_M (Thin QFP, 100-Leads, Body 14x14mm, Pitch 0.5mm, IPC Low Density)
3D model CY7C09079A-A100 (100-Pin Thin Quad Flat Pack 0.5 mm Pitch)
pins: 1 NC, 2 NC, 3 A7L (in), 4 A8L (in), 5 A9L (in), 6 A10L (in), 7 A11L (in), 8 A12L (in), 9 A13L (in), 10 A14L (in), 11 NC, 12 NC, 13 VCC (power), 14 NC, 15 NC, 16 NC, 17 NC, 18 ~{CE}0L (in), 19 CE1L (in), 20 ~{CNTRST}L (in), 21 R/~{W}L (in), 22 ~{OE}L (in), 23 ~{FT}/PIPEL (in), 24 NC, 25 NC, 26 GND (power), 27 NC, 28 I/O7L (io), 29 I/O6L (io), 30 I/O5L (io), 31 I/O4L (io), 32 I/O3L (io), 33 I/O2L (io), 34 GND (power), 35 I/O1L (io), 36 I/O0L (io), 37 VCC (power), 38 GND (power), 39 I/O0R (io), 40 I/O1R (io), 41 I/O2R (io), 42 VCC (power), 43 I/O3R (io), 44 I/O4R (io), 45 I/O5R (io), 46 I/O6R (io), 47 I/O7R (io), 48 NC, 49 NC, 50 NC, 51 NC, 52 GND (power), 53 ~{FT}/PIPER (in), 54 ~{OE}R (in), 55 R/~{W}R (in), 56 ~{CNTRST}R (in), 57 CE1R (in), 58 ~{CE}0R (in), 59 NC, 60 NC, 61 NC, 62 NC, 63 GND (power), 64 NC, 65 NC, 66 A14R (in), 67 A13R (in), 68 A12R (in), 69 A11R (in), 70 A10R (in), 71 A9R (in), 72 A8R (in), 73 A7R (in), 74 NC, 75 NC, 76 NC, 77 NC, 78 A6R (in), 79 A5R (in), 80 A4R (in), 81 A3R (in), 82 A2R (in), 83 A1R (in), 84 A0R (in), 85 ~{CNTEN}R (in), 86 CLKR (in), 87 ~{ADS}R (in), 88 GND (power), 89 ~{ADS}L (in), 90 CLKL (in), 91 ~{CNTEN}L (in), 92 A0L (in), 93 A1L (in), 94 A2L (in), 95 A3L (in), 96 A4L (in), 97 A5L (in), 98 A6L (in), 99 NC, 100 NC

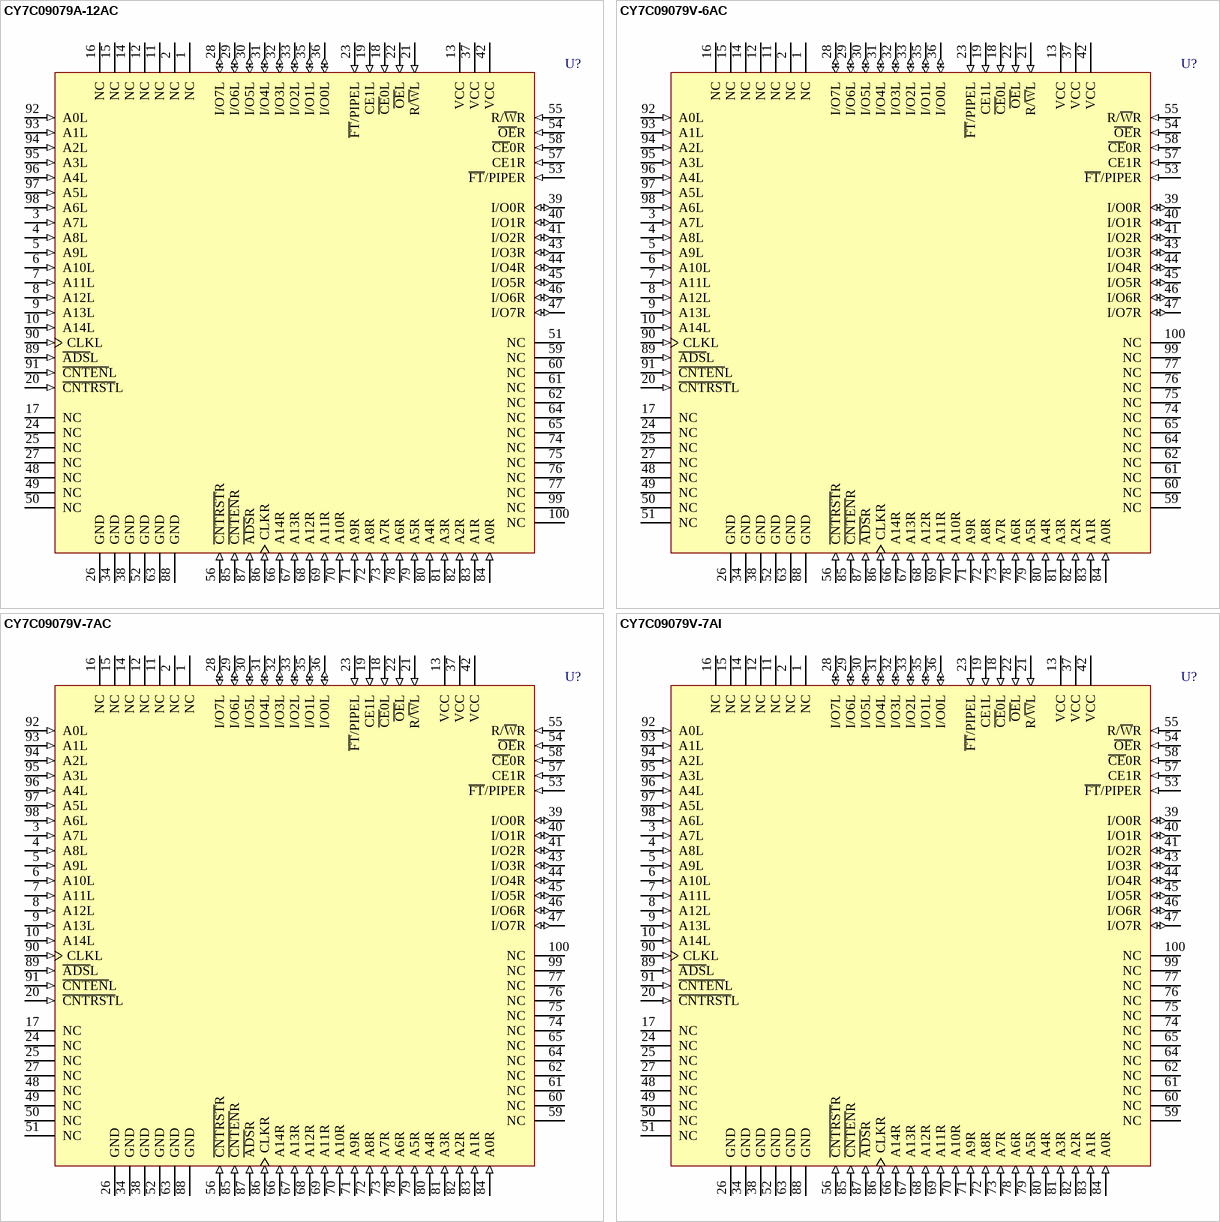
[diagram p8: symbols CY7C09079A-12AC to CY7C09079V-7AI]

## CY7C09079A-12AC
designator U?
32K x 8 Synchronous Dual-Port RAM
footprint A100_N (Thin QFP, 100-Leads, Body 14x14mm, Pitch 0.5mm, IPC Medium Density)
footprint A100_L (Thin QFP, 100-Leads, Body 14x14mm, Pitch 0.5mm, IPC High Density)
footprint A100_M (Thin QFP, 100-Leads, Body 14x14mm, Pitch 0.5mm, IPC Low Density)
3D model CY7C09079A-A100 (100-Pin Thin Quad Flat Pack 0.5 mm Pitch)
pins: 1 NC, 2 NC, 3 A7L (in), 4 A8L (in), 5 A9L (in), 6 A10L (in), 7 A11L (in), 8 A12L (in), 9 A13L (in), 10 A14L (in), 11 NC, 12 NC, 13 VCC (power), 14 NC, 15 NC, 16 NC, 17 NC, 18 ~{CE}0L (in), 19 CE1L (in), 20 ~{CNTRST}L (in), 21 R/~{W}L (in), 22 ~{OE}L (in), 23 ~{FT}/PIPEL (in), 24 NC, 25 NC, 26 GND (power), 27 NC, 28 I/O7L (io), 29 I/O6L (io), 30 I/O5L (io), 31 I/O4L (io), 32 I/O3L (io), 33 I/O2L (io), 34 GND (power), 35 I/O1L (io), 36 I/O0L (io), 37 VCC (power), 38 GND (power), 39 I/O0R (io), 40 I/O1R (io), 41 I/O2R (io), 42 VCC (power), 43 I/O3R (io), 44 I/O4R (io), 45 I/O5R (io), 46 I/O6R (io), 47 I/O7R (io), 48 NC, 49 NC, 50 NC, 51 NC, 52 GND (power), 53 ~{FT}/PIPER (in), 54 ~{OE}R (in), 55 R/~{W}R (in), 56 ~{CNTRST}R (in), 57 CE1R (in), 58 ~{CE}0R (in), 59 NC, 60 NC, 61 NC, 62 NC, 63 GND (power), 64 NC, 65 NC, 66 A14R (in), 67 A13R (in), 68 A12R (in), 69 A11R (in), 70 A10R (in), 71 A9R (in), 72 A8R (in), 73 A7R (in), 74 NC, 75 NC, 76 NC, 77 NC, 78 A6R (in), 79 A5R (in), 80 A4R (in), 81 A3R (in), 82 A2R (in), 83 A1R (in), 84 A0R (in), 85 ~{CNTEN}R (in), 86 CLKR (in), 87 ~{ADS}R (in), 88 GND (power), 89 ~{ADS}L (in), 90 CLKL (in), 91 ~{CNTEN}L (in), 92 A0L (in), 93 A1L (in), 94 A2L (in), 95 A3L (in), 96 A4L (in), 97 A5L (in), 98 A6L (in), 99 NC, 100 NC

## CY7C09079V-6AC
designator U?
3.3V 32K x 8 Synchronous Dual-Port Static RAM
footprint A100_N (Thin QFP, 100-Leads, Body 14x14mm, Pitch 0.5mm, IPC Medium Density)
footprint A100_L (Thin QFP, 100-Leads, Body 14x14mm, Pitch 0.5mm, IPC High Density)
footprint A100_M (Thin QFP, 100-Leads, Body 14x14mm, Pitch 0.5mm, IPC Low Density)
3D model CY7C09079V-A100 (100-Pin Thin Quad Flat Pack 0.5 mm Pitch)
pins: 1 NC, 2 NC, 3 A7L (in), 4 A8L (in), 5 A9L (in), 6 A10L (in), 7 A11L (in), 8 A12L (in), 9 A13L (in), 10 A14L (in), 11 NC, 12 NC, 13 VCC (power), 14 NC, 15 NC, 16 NC, 17 NC, 18 ~{CE}0L (in), 19 CE1L (in), 20 ~{CNTRST}L (in), 21 R/~{W}L (in), 22 ~{OE}L (in), 23 ~{FT}/PIPEL (in), 24 NC, 25 NC, 26 GND (power), 27 NC, 28 I/O7L (io), 29 I/O6L (io), 30 I/O5L (io), 31 I/O4L (io), 32 I/O3L (io), 33 I/O2L (io), 34 GND (power), 35 I/O1L (io), 36 I/O0L (io), 37 VCC (power), 38 GND (power), 39 I/O0R (io), 40 I/O1R (io), 41 I/O2R (io), 42 VCC (power), 43 I/O3R (io), 44 I/O4R (io), 45 I/O5R (io), 46 I/O6R (io), 47 I/O7R (io), 48 NC, 49 NC, 50 NC, 51 NC, 52 GND (power), 53 ~{FT}/PIPER (in), 54 ~{OE}R (in), 55 R/~{W}R (in), 56 ~{CNTRST}R (in), 57 CE1R (in), 58 ~{CE}0R (in), 59 NC, 60 NC, 61 NC, 62 NC, 63 GND (power), 64 NC, 65 NC, 66 A14R (in), 67 A13R (in), 68 A12R (in), 69 A11R (in), 70 A10R (in), 71 A9R (in), 72 A8R (in), 73 A7R (in), 74 NC, 75 NC, 76 NC, 77 NC, 78 A6R (in), 79 A5R (in), 80 A4R (in), 81 A3R (in), 82 A2R (in), 83 A1R (in), 84 A0R (in), 85 ~{CNTEN}R (in), 86 CLKR (in), 87 ~{ADS}R (in), 88 GND (power), 89 ~{ADS}L (in), 90 CLKL (in), 91 ~{CNTEN}L (in), 92 A0L (in), 93 A1L (in), 94 A2L (in), 95 A3L (in), 96 A4L (in), 97 A5L (in), 98 A6L (in), 99 NC, 100 NC

## CY7C09079V-7AC
designator U?
3.3V 32K x 8 Synchronous Dual-Port Static RAM
footprint A100_N (Thin QFP, 100-Leads, Body 14x14mm, Pitch 0.5mm, IPC Medium Density)
footprint A100_L (Thin QFP, 100-Leads, Body 14x14mm, Pitch 0.5mm, IPC High Density)
footprint A100_M (Thin QFP, 100-Leads, Body 14x14mm, Pitch 0.5mm, IPC Low Density)
3D model CY7C09079V-A100 (100-Pin Thin Quad Flat Pack 0.5 mm Pitch)
pins: 1 NC, 2 NC, 3 A7L (in), 4 A8L (in), 5 A9L (in), 6 A10L (in), 7 A11L (in), 8 A12L (in), 9 A13L (in), 10 A14L (in), 11 NC, 12 NC, 13 VCC (power), 14 NC, 15 NC, 16 NC, 17 NC, 18 ~{CE}0L (in), 19 CE1L (in), 20 ~{CNTRST}L (in), 21 R/~{W}L (in), 22 ~{OE}L (in), 23 ~{FT}/PIPEL (in), 24 NC, 25 NC, 26 GND (power), 27 NC, 28 I/O7L (io), 29 I/O6L (io), 30 I/O5L (io), 31 I/O4L (io), 32 I/O3L (io), 33 I/O2L (io), 34 GND (power), 35 I/O1L (io), 36 I/O0L (io), 37 VCC (power), 38 GND (power), 39 I/O0R (io), 40 I/O1R (io), 41 I/O2R (io), 42 VCC (power), 43 I/O3R (io), 44 I/O4R (io), 45 I/O5R (io), 46 I/O6R (io), 47 I/O7R (io), 48 NC, 49 NC, 50 NC, 51 NC, 52 GND (power), 53 ~{FT}/PIPER (in), 54 ~{OE}R (in), 55 R/~{W}R (in), 56 ~{CNTRST}R (in), 57 CE1R (in), 58 ~{CE}0R (in), 59 NC, 60 NC, 61 NC, 62 NC, 63 GND (power), 64 NC, 65 NC, 66 A14R (in), 67 A13R (in), 68 A12R (in), 69 A11R (in), 70 A10R (in), 71 A9R (in), 72 A8R (in), 73 A7R (in), 74 NC, 75 NC, 76 NC, 77 NC, 78 A6R (in), 79 A5R (in), 80 A4R (in), 81 A3R (in), 82 A2R (in), 83 A1R (in), 84 A0R (in), 85 ~{CNTEN}R (in), 86 CLKR (in), 87 ~{ADS}R (in), 88 GND (power), 89 ~{ADS}L (in), 90 CLKL (in), 91 ~{CNTEN}L (in), 92 A0L (in), 93 A1L (in), 94 A2L (in), 95 A3L (in), 96 A4L (in), 97 A5L (in), 98 A6L (in), 99 NC, 100 NC

## CY7C09079V-7AI
designator U?
3.3V 32K x 8 Synchronous Dual-Port Static RAM
footprint A100_N (Thin QFP, 100-Leads, Body 14x14mm, Pitch 0.5mm, IPC Medium Density)
footprint A100_L (Thin QFP, 100-Leads, Body 14x14mm, Pitch 0.5mm, IPC High Density)
footprint A100_M (Thin QFP, 100-Leads, Body 14x14mm, Pitch 0.5mm, IPC Low Density)
3D model CY7C09079V-A100 (100-Pin Thin Quad Flat Pack 0.5 mm Pitch)
pins: 1 NC, 2 NC, 3 A7L (in), 4 A8L (in), 5 A9L (in), 6 A10L (in), 7 A11L (in), 8 A12L (in), 9 A13L (in), 10 A14L (in), 11 NC, 12 NC, 13 VCC (power), 14 NC, 15 NC, 16 NC, 17 NC, 18 ~{CE}0L (in), 19 CE1L (in), 20 ~{CNTRST}L (in), 21 R/~{W}L (in), 22 ~{OE}L (in), 23 ~{FT}/PIPEL (in), 24 NC, 25 NC, 26 GND (power), 27 NC, 28 I/O7L (io), 29 I/O6L (io), 30 I/O5L (io), 31 I/O4L (io), 32 I/O3L (io), 33 I/O2L (io), 34 GND (power), 35 I/O1L (io), 36 I/O0L (io), 37 VCC (power), 38 GND (power), 39 I/O0R (io), 40 I/O1R (io), 41 I/O2R (io), 42 VCC (power), 43 I/O3R (io), 44 I/O4R (io), 45 I/O5R (io), 46 I/O6R (io), 47 I/O7R (io), 48 NC, 49 NC, 50 NC, 51 NC, 52 GND (power), 53 ~{FT}/PIPER (in), 54 ~{OE}R (in), 55 R/~{W}R (in), 56 ~{CNTRST}R (in), 57 CE1R (in), 58 ~{CE}0R (in), 59 NC, 60 NC, 61 NC, 62 NC, 63 GND (power), 64 NC, 65 NC, 66 A14R (in), 67 A13R (in), 68 A12R (in), 69 A11R (in), 70 A10R (in), 71 A9R (in), 72 A8R (in), 73 A7R (in), 74 NC, 75 NC, 76 NC, 77 NC, 78 A6R (in), 79 A5R (in), 80 A4R (in), 81 A3R (in), 82 A2R (in), 83 A1R (in), 84 A0R (in), 85 ~{CNTEN}R (in), 86 CLKR (in), 87 ~{ADS}R (in), 88 GND (power), 89 ~{ADS}L (in), 90 CLKL (in), 91 ~{CNTEN}L (in), 92 A0L (in), 93 A1L (in), 94 A2L (in), 95 A3L (in), 96 A4L (in), 97 A5L (in), 98 A6L (in), 99 NC, 100 NC

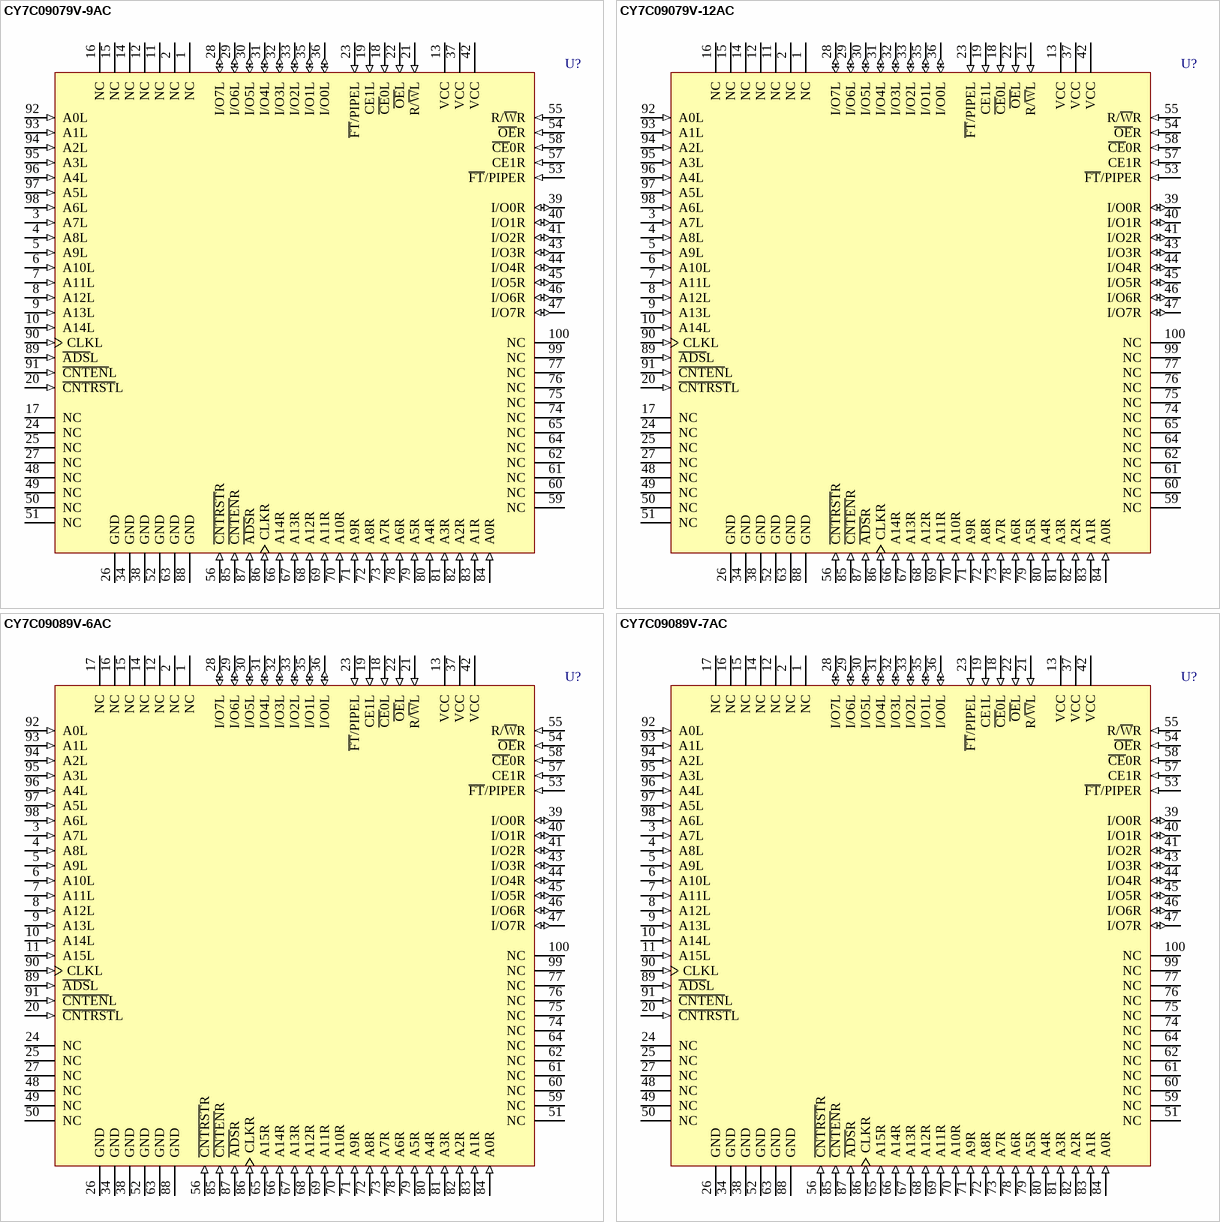
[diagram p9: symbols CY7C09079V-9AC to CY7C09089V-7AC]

## CY7C09079V-9AC
designator U?
3.3V 32K x 8 Synchronous Dual-Port Static RAM
footprint A100_N (Thin QFP, 100-Leads, Body 14x14mm, Pitch 0.5mm, IPC Medium Density)
footprint A100_L (Thin QFP, 100-Leads, Body 14x14mm, Pitch 0.5mm, IPC High Density)
footprint A100_M (Thin QFP, 100-Leads, Body 14x14mm, Pitch 0.5mm, IPC Low Density)
3D model CY7C09079V-A100 (100-Pin Thin Quad Flat Pack 0.5 mm Pitch)
pins: 1 NC, 2 NC, 3 A7L (in), 4 A8L (in), 5 A9L (in), 6 A10L (in), 7 A11L (in), 8 A12L (in), 9 A13L (in), 10 A14L (in), 11 NC, 12 NC, 13 VCC (power), 14 NC, 15 NC, 16 NC, 17 NC, 18 ~{CE}0L (in), 19 CE1L (in), 20 ~{CNTRST}L (in), 21 R/~{W}L (in), 22 ~{OE}L (in), 23 ~{FT}/PIPEL (in), 24 NC, 25 NC, 26 GND (power), 27 NC, 28 I/O7L (io), 29 I/O6L (io), 30 I/O5L (io), 31 I/O4L (io), 32 I/O3L (io), 33 I/O2L (io), 34 GND (power), 35 I/O1L (io), 36 I/O0L (io), 37 VCC (power), 38 GND (power), 39 I/O0R (io), 40 I/O1R (io), 41 I/O2R (io), 42 VCC (power), 43 I/O3R (io), 44 I/O4R (io), 45 I/O5R (io), 46 I/O6R (io), 47 I/O7R (io), 48 NC, 49 NC, 50 NC, 51 NC, 52 GND (power), 53 ~{FT}/PIPER (in), 54 ~{OE}R (in), 55 R/~{W}R (in), 56 ~{CNTRST}R (in), 57 CE1R (in), 58 ~{CE}0R (in), 59 NC, 60 NC, 61 NC, 62 NC, 63 GND (power), 64 NC, 65 NC, 66 A14R (in), 67 A13R (in), 68 A12R (in), 69 A11R (in), 70 A10R (in), 71 A9R (in), 72 A8R (in), 73 A7R (in), 74 NC, 75 NC, 76 NC, 77 NC, 78 A6R (in), 79 A5R (in), 80 A4R (in), 81 A3R (in), 82 A2R (in), 83 A1R (in), 84 A0R (in), 85 ~{CNTEN}R (in), 86 CLKR (in), 87 ~{ADS}R (in), 88 GND (power), 89 ~{ADS}L (in), 90 CLKL (in), 91 ~{CNTEN}L (in), 92 A0L (in), 93 A1L (in), 94 A2L (in), 95 A3L (in), 96 A4L (in), 97 A5L (in), 98 A6L (in), 99 NC, 100 NC

## CY7C09079V-12AC
designator U?
3.3V 32K x 8 Synchronous Dual-Port Static RAM
footprint A100_N (Thin QFP, 100-Leads, Body 14x14mm, Pitch 0.5mm, IPC Medium Density)
footprint A100_L (Thin QFP, 100-Leads, Body 14x14mm, Pitch 0.5mm, IPC High Density)
footprint A100_M (Thin QFP, 100-Leads, Body 14x14mm, Pitch 0.5mm, IPC Low Density)
3D model CY7C09079V-A100 (100-Pin Thin Quad Flat Pack 0.5 mm Pitch)
pins: 1 NC, 2 NC, 3 A7L (in), 4 A8L (in), 5 A9L (in), 6 A10L (in), 7 A11L (in), 8 A12L (in), 9 A13L (in), 10 A14L (in), 11 NC, 12 NC, 13 VCC (power), 14 NC, 15 NC, 16 NC, 17 NC, 18 ~{CE}0L (in), 19 CE1L (in), 20 ~{CNTRST}L (in), 21 R/~{W}L (in), 22 ~{OE}L (in), 23 ~{FT}/PIPEL (in), 24 NC, 25 NC, 26 GND (power), 27 NC, 28 I/O7L (io), 29 I/O6L (io), 30 I/O5L (io), 31 I/O4L (io), 32 I/O3L (io), 33 I/O2L (io), 34 GND (power), 35 I/O1L (io), 36 I/O0L (io), 37 VCC (power), 38 GND (power), 39 I/O0R (io), 40 I/O1R (io), 41 I/O2R (io), 42 VCC (power), 43 I/O3R (io), 44 I/O4R (io), 45 I/O5R (io), 46 I/O6R (io), 47 I/O7R (io), 48 NC, 49 NC, 50 NC, 51 NC, 52 GND (power), 53 ~{FT}/PIPER (in), 54 ~{OE}R (in), 55 R/~{W}R (in), 56 ~{CNTRST}R (in), 57 CE1R (in), 58 ~{CE}0R (in), 59 NC, 60 NC, 61 NC, 62 NC, 63 GND (power), 64 NC, 65 NC, 66 A14R (in), 67 A13R (in), 68 A12R (in), 69 A11R (in), 70 A10R (in), 71 A9R (in), 72 A8R (in), 73 A7R (in), 74 NC, 75 NC, 76 NC, 77 NC, 78 A6R (in), 79 A5R (in), 80 A4R (in), 81 A3R (in), 82 A2R (in), 83 A1R (in), 84 A0R (in), 85 ~{CNTEN}R (in), 86 CLKR (in), 87 ~{ADS}R (in), 88 GND (power), 89 ~{ADS}L (in), 90 CLKL (in), 91 ~{CNTEN}L (in), 92 A0L (in), 93 A1L (in), 94 A2L (in), 95 A3L (in), 96 A4L (in), 97 A5L (in), 98 A6L (in), 99 NC, 100 NC

## CY7C09089V-6AC
designator U?
3.3V 64K x 8 Synchronous Dual-Port Static RAM
footprint A100_N (Thin QFP, 100-Leads, Body 14x14mm, Pitch 0.5mm, IPC Medium Density)
footprint A100_L (Thin QFP, 100-Leads, Body 14x14mm, Pitch 0.5mm, IPC High Density)
footprint A100_M (Thin QFP, 100-Leads, Body 14x14mm, Pitch 0.5mm, IPC Low Density)
3D model CY7C09089V-A100 (100-Pin Thin Quad Flat Pack 0.5 mm Pitch)
pins: 1 NC, 2 NC, 3 A7L (in), 4 A8L (in), 5 A9L (in), 6 A10L (in), 7 A11L (in), 8 A12L (in), 9 A13L (in), 10 A14L (in), 11 A15L (in), 12 NC, 13 VCC (power), 14 NC, 15 NC, 16 NC, 17 NC, 18 ~{CE}0L (in), 19 CE1L (in), 20 ~{CNTRST}L (in), 21 R/~{W}L (in), 22 ~{OE}L (in), 23 ~{FT}/PIPEL (in), 24 NC, 25 NC, 26 GND (power), 27 NC, 28 I/O7L (io), 29 I/O6L (io), 30 I/O5L (io), 31 I/O4L (io), 32 I/O3L (io), 33 I/O2L (io), 34 GND (power), 35 I/O1L (io), 36 I/O0L (io), 37 VCC (power), 38 GND (power), 39 I/O0R (io), 40 I/O1R (io), 41 I/O2R (io), 42 VCC (power), 43 I/O3R (io), 44 I/O4R (io), 45 I/O5R (io), 46 I/O6R (io), 47 I/O7R (io), 48 NC, 49 NC, 50 NC, 51 NC, 52 GND (power), 53 ~{FT}/PIPER (in), 54 ~{OE}R (in), 55 R/~{W}R (in), 56 ~{CNTRST}R (in), 57 CE1R (in), 58 ~{CE}0R (in), 59 NC, 60 NC, 61 NC, 62 NC, 63 GND (power), 64 NC, 65 A15R (in), 66 A14R (in), 67 A13R (in), 68 A12R (in), 69 A11R (in), 70 A10R (in), 71 A9R (in), 72 A8R (in), 73 A7R (in), 74 NC, 75 NC, 76 NC, 77 NC, 78 A6R (in), 79 A5R (in), 80 A4R (in), 81 A3R (in), 82 A2R (in), 83 A1R (in), 84 A0R (in), 85 ~{CNTEN}R (in), 86 CLKR (in), 87 ~{ADS}R (in), 88 GND (power), 89 ~{ADS}L (in), 90 CLKL (in), 91 ~{CNTEN}L (in), 92 A0L (in), 93 A1L (in), 94 A2L (in), 95 A3L (in), 96 A4L (in), 97 A5L (in), 98 A6L (in), 99 NC, 100 NC

## CY7C09089V-7AC
designator U?
3.3V 64K x 8 Synchronous Dual-Port Static RAM
footprint A100_N (Thin QFP, 100-Leads, Body 14x14mm, Pitch 0.5mm, IPC Medium Density)
footprint A100_L (Thin QFP, 100-Leads, Body 14x14mm, Pitch 0.5mm, IPC High Density)
footprint A100_M (Thin QFP, 100-Leads, Body 14x14mm, Pitch 0.5mm, IPC Low Density)
3D model CY7C09089V-A100 (100-Pin Thin Quad Flat Pack 0.5 mm Pitch)
pins: 1 NC, 2 NC, 3 A7L (in), 4 A8L (in), 5 A9L (in), 6 A10L (in), 7 A11L (in), 8 A12L (in), 9 A13L (in), 10 A14L (in), 11 A15L (in), 12 NC, 13 VCC (power), 14 NC, 15 NC, 16 NC, 17 NC, 18 ~{CE}0L (in), 19 CE1L (in), 20 ~{CNTRST}L (in), 21 R/~{W}L (in), 22 ~{OE}L (in), 23 ~{FT}/PIPEL (in), 24 NC, 25 NC, 26 GND (power), 27 NC, 28 I/O7L (io), 29 I/O6L (io), 30 I/O5L (io), 31 I/O4L (io), 32 I/O3L (io), 33 I/O2L (io), 34 GND (power), 35 I/O1L (io), 36 I/O0L (io), 37 VCC (power), 38 GND (power), 39 I/O0R (io), 40 I/O1R (io), 41 I/O2R (io), 42 VCC (power), 43 I/O3R (io), 44 I/O4R (io), 45 I/O5R (io), 46 I/O6R (io), 47 I/O7R (io), 48 NC, 49 NC, 50 NC, 51 NC, 52 GND (power), 53 ~{FT}/PIPER (in), 54 ~{OE}R (in), 55 R/~{W}R (in), 56 ~{CNTRST}R (in), 57 CE1R (in), 58 ~{CE}0R (in), 59 NC, 60 NC, 61 NC, 62 NC, 63 GND (power), 64 NC, 65 A15R (in), 66 A14R (in), 67 A13R (in), 68 A12R (in), 69 A11R (in), 70 A10R (in), 71 A9R (in), 72 A8R (in), 73 A7R (in), 74 NC, 75 NC, 76 NC, 77 NC, 78 A6R (in), 79 A5R (in), 80 A4R (in), 81 A3R (in), 82 A2R (in), 83 A1R (in), 84 A0R (in), 85 ~{CNTEN}R (in), 86 CLKR (in), 87 ~{ADS}R (in), 88 GND (power), 89 ~{ADS}L (in), 90 CLKL (in), 91 ~{CNTEN}L (in), 92 A0L (in), 93 A1L (in), 94 A2L (in), 95 A3L (in), 96 A4L (in), 97 A5L (in), 98 A6L (in), 99 NC, 100 NC

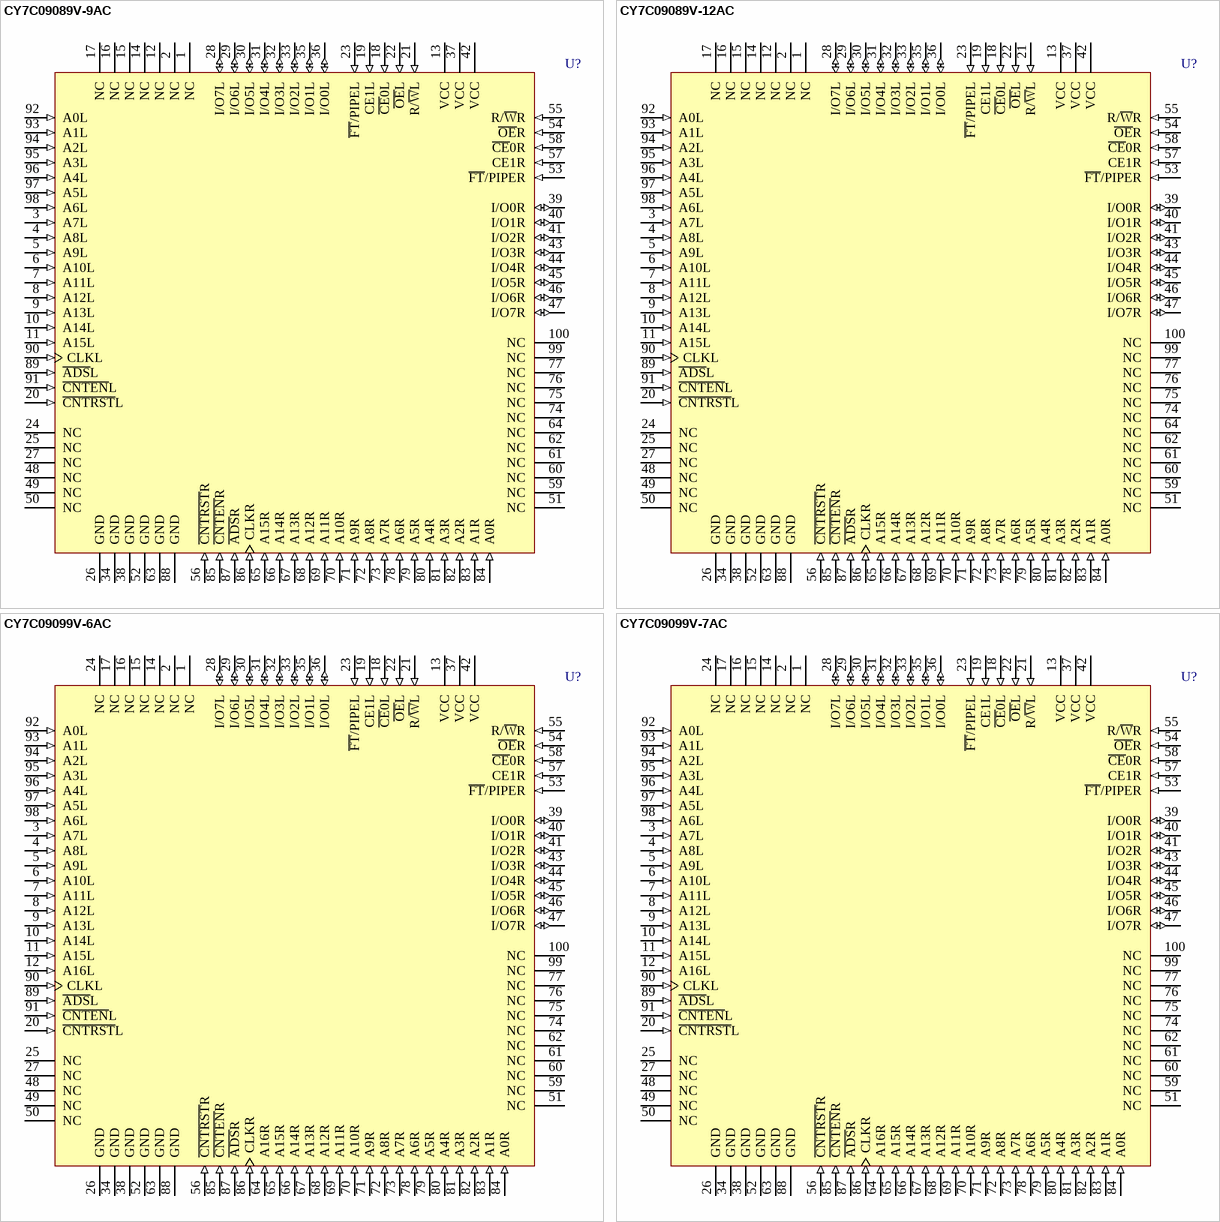
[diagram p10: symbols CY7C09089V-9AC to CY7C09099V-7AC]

## CY7C09089V-9AC
designator U?
3.3V 64K x 8 Synchronous Dual-Port Static RAM
footprint A100_N (Thin QFP, 100-Leads, Body 14x14mm, Pitch 0.5mm, IPC Medium Density)
footprint A100_L (Thin QFP, 100-Leads, Body 14x14mm, Pitch 0.5mm, IPC High Density)
footprint A100_M (Thin QFP, 100-Leads, Body 14x14mm, Pitch 0.5mm, IPC Low Density)
3D model CY7C09089V-A100 (100-Pin Thin Quad Flat Pack 0.5 mm Pitch)
pins: 1 NC, 2 NC, 3 A7L (in), 4 A8L (in), 5 A9L (in), 6 A10L (in), 7 A11L (in), 8 A12L (in), 9 A13L (in), 10 A14L (in), 11 A15L (in), 12 NC, 13 VCC (power), 14 NC, 15 NC, 16 NC, 17 NC, 18 ~{CE}0L (in), 19 CE1L (in), 20 ~{CNTRST}L (in), 21 R/~{W}L (in), 22 ~{OE}L (in), 23 ~{FT}/PIPEL (in), 24 NC, 25 NC, 26 GND (power), 27 NC, 28 I/O7L (io), 29 I/O6L (io), 30 I/O5L (io), 31 I/O4L (io), 32 I/O3L (io), 33 I/O2L (io), 34 GND (power), 35 I/O1L (io), 36 I/O0L (io), 37 VCC (power), 38 GND (power), 39 I/O0R (io), 40 I/O1R (io), 41 I/O2R (io), 42 VCC (power), 43 I/O3R (io), 44 I/O4R (io), 45 I/O5R (io), 46 I/O6R (io), 47 I/O7R (io), 48 NC, 49 NC, 50 NC, 51 NC, 52 GND (power), 53 ~{FT}/PIPER (in), 54 ~{OE}R (in), 55 R/~{W}R (in), 56 ~{CNTRST}R (in), 57 CE1R (in), 58 ~{CE}0R (in), 59 NC, 60 NC, 61 NC, 62 NC, 63 GND (power), 64 NC, 65 A15R (in), 66 A14R (in), 67 A13R (in), 68 A12R (in), 69 A11R (in), 70 A10R (in), 71 A9R (in), 72 A8R (in), 73 A7R (in), 74 NC, 75 NC, 76 NC, 77 NC, 78 A6R (in), 79 A5R (in), 80 A4R (in), 81 A3R (in), 82 A2R (in), 83 A1R (in), 84 A0R (in), 85 ~{CNTEN}R (in), 86 CLKR (in), 87 ~{ADS}R (in), 88 GND (power), 89 ~{ADS}L (in), 90 CLKL (in), 91 ~{CNTEN}L (in), 92 A0L (in), 93 A1L (in), 94 A2L (in), 95 A3L (in), 96 A4L (in), 97 A5L (in), 98 A6L (in), 99 NC, 100 NC

## CY7C09089V-12AC
designator U?
3.3V 64K x 8 Synchronous Dual-Port Static RAM
footprint A100_N (Thin QFP, 100-Leads, Body 14x14mm, Pitch 0.5mm, IPC Medium Density)
footprint A100_L (Thin QFP, 100-Leads, Body 14x14mm, Pitch 0.5mm, IPC High Density)
footprint A100_M (Thin QFP, 100-Leads, Body 14x14mm, Pitch 0.5mm, IPC Low Density)
3D model CY7C09089V-A100 (100-Pin Thin Quad Flat Pack 0.5 mm Pitch)
pins: 1 NC, 2 NC, 3 A7L (in), 4 A8L (in), 5 A9L (in), 6 A10L (in), 7 A11L (in), 8 A12L (in), 9 A13L (in), 10 A14L (in), 11 A15L (in), 12 NC, 13 VCC (power), 14 NC, 15 NC, 16 NC, 17 NC, 18 ~{CE}0L (in), 19 CE1L (in), 20 ~{CNTRST}L (in), 21 R/~{W}L (in), 22 ~{OE}L (in), 23 ~{FT}/PIPEL (in), 24 NC, 25 NC, 26 GND (power), 27 NC, 28 I/O7L (io), 29 I/O6L (io), 30 I/O5L (io), 31 I/O4L (io), 32 I/O3L (io), 33 I/O2L (io), 34 GND (power), 35 I/O1L (io), 36 I/O0L (io), 37 VCC (power), 38 GND (power), 39 I/O0R (io), 40 I/O1R (io), 41 I/O2R (io), 42 VCC (power), 43 I/O3R (io), 44 I/O4R (io), 45 I/O5R (io), 46 I/O6R (io), 47 I/O7R (io), 48 NC, 49 NC, 50 NC, 51 NC, 52 GND (power), 53 ~{FT}/PIPER (in), 54 ~{OE}R (in), 55 R/~{W}R (in), 56 ~{CNTRST}R (in), 57 CE1R (in), 58 ~{CE}0R (in), 59 NC, 60 NC, 61 NC, 62 NC, 63 GND (power), 64 NC, 65 A15R (in), 66 A14R (in), 67 A13R (in), 68 A12R (in), 69 A11R (in), 70 A10R (in), 71 A9R (in), 72 A8R (in), 73 A7R (in), 74 NC, 75 NC, 76 NC, 77 NC, 78 A6R (in), 79 A5R (in), 80 A4R (in), 81 A3R (in), 82 A2R (in), 83 A1R (in), 84 A0R (in), 85 ~{CNTEN}R (in), 86 CLKR (in), 87 ~{ADS}R (in), 88 GND (power), 89 ~{ADS}L (in), 90 CLKL (in), 91 ~{CNTEN}L (in), 92 A0L (in), 93 A1L (in), 94 A2L (in), 95 A3L (in), 96 A4L (in), 97 A5L (in), 98 A6L (in), 99 NC, 100 NC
